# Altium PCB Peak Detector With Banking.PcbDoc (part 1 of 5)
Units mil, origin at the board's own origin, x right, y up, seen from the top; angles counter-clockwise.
Board outline 3330 x 2725 mil, 4 copper layers (TopLayer, GROUND, MidLayer1, BottomLayer); 549 components, 391 nets, 1594 pads, 460 vias.
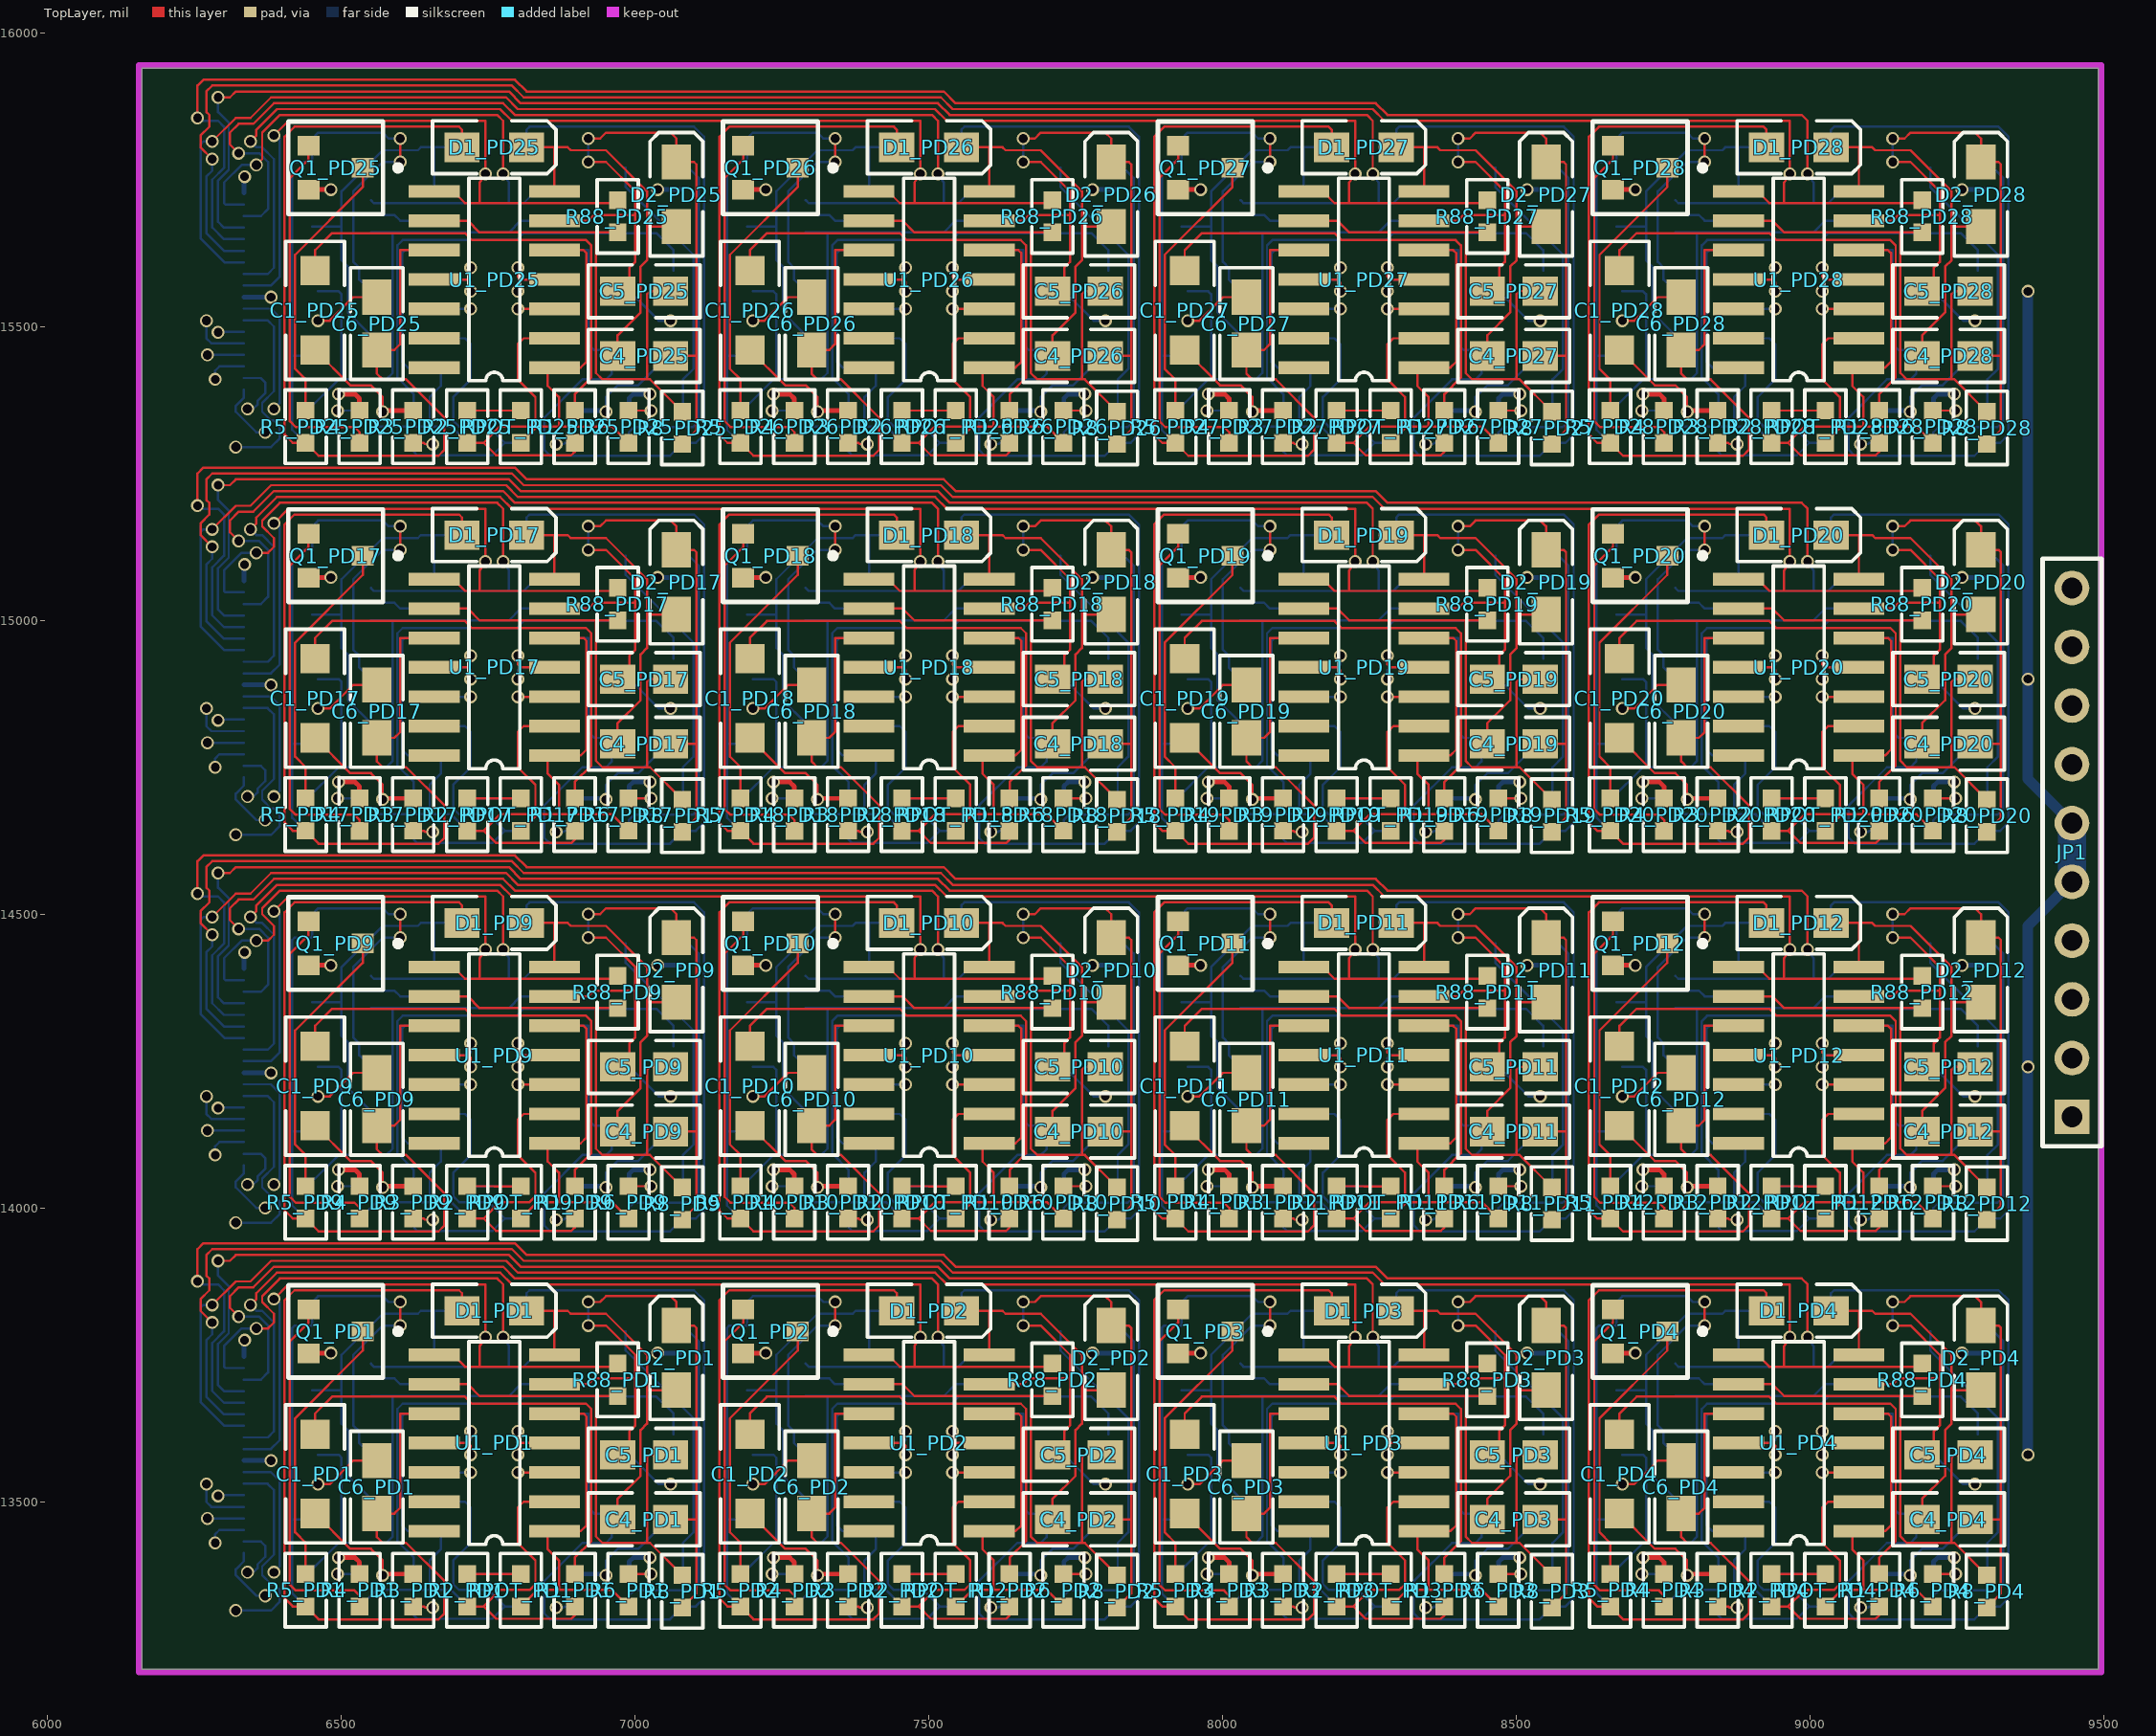
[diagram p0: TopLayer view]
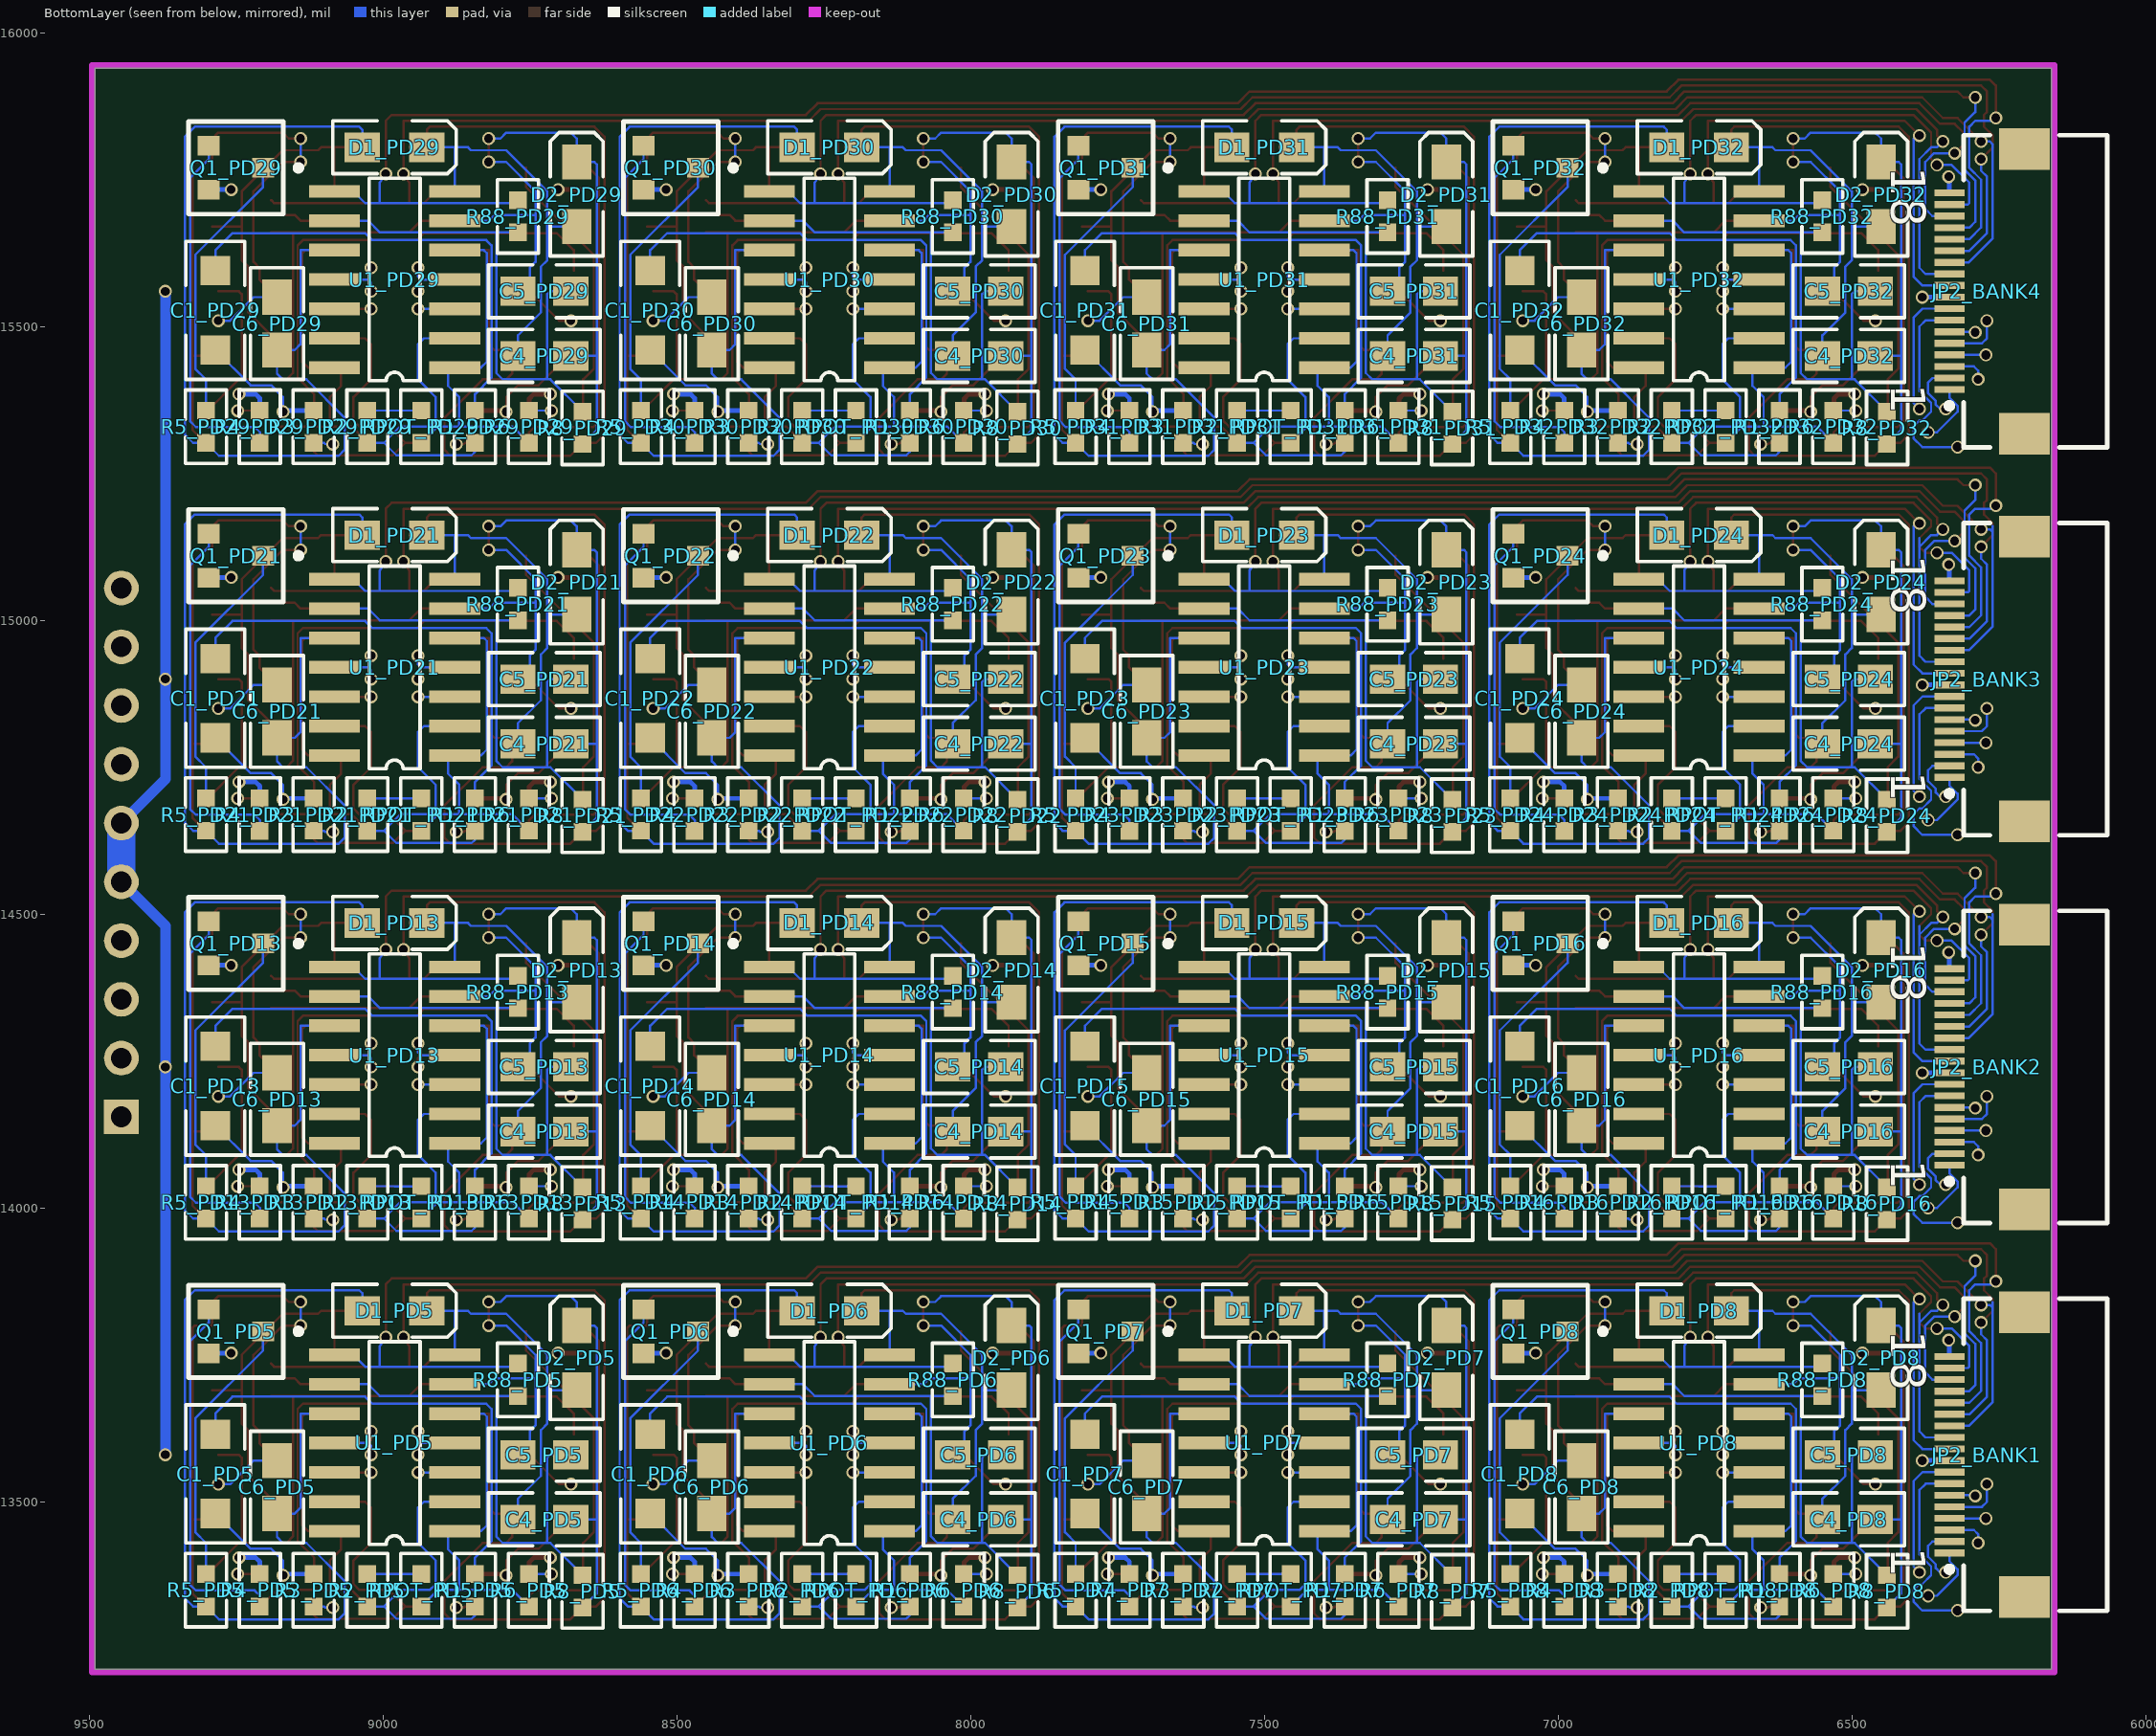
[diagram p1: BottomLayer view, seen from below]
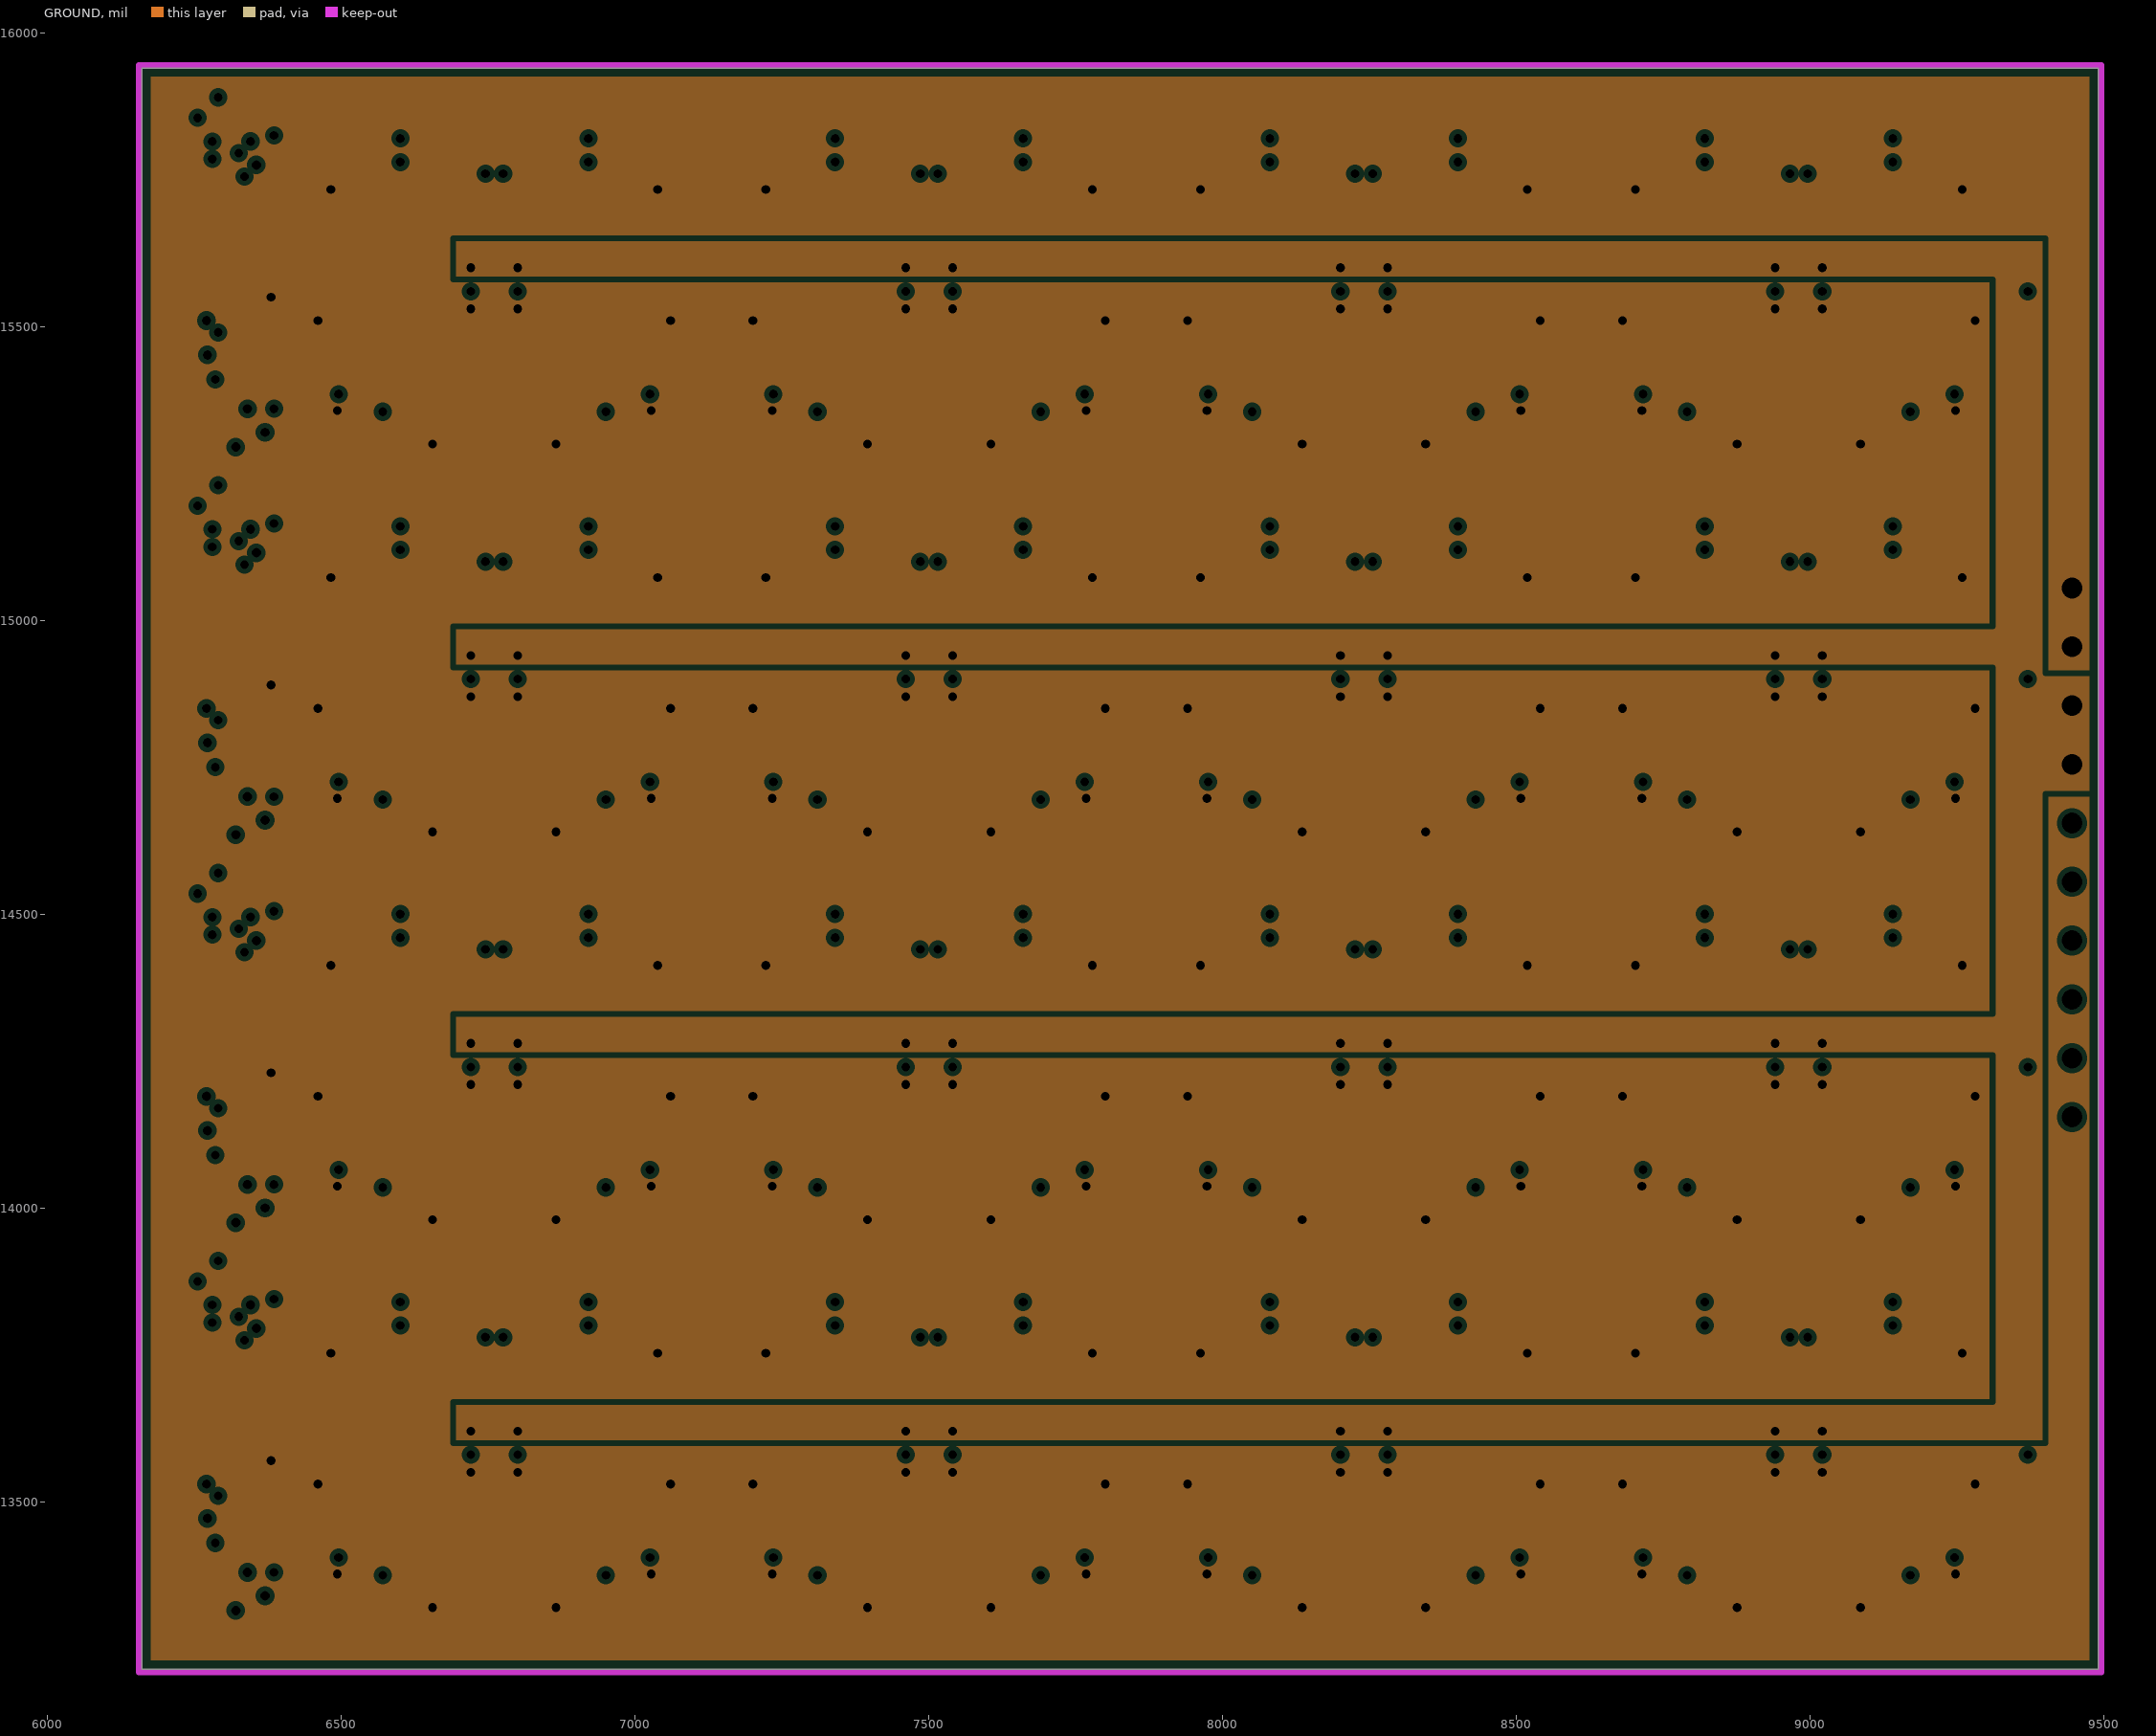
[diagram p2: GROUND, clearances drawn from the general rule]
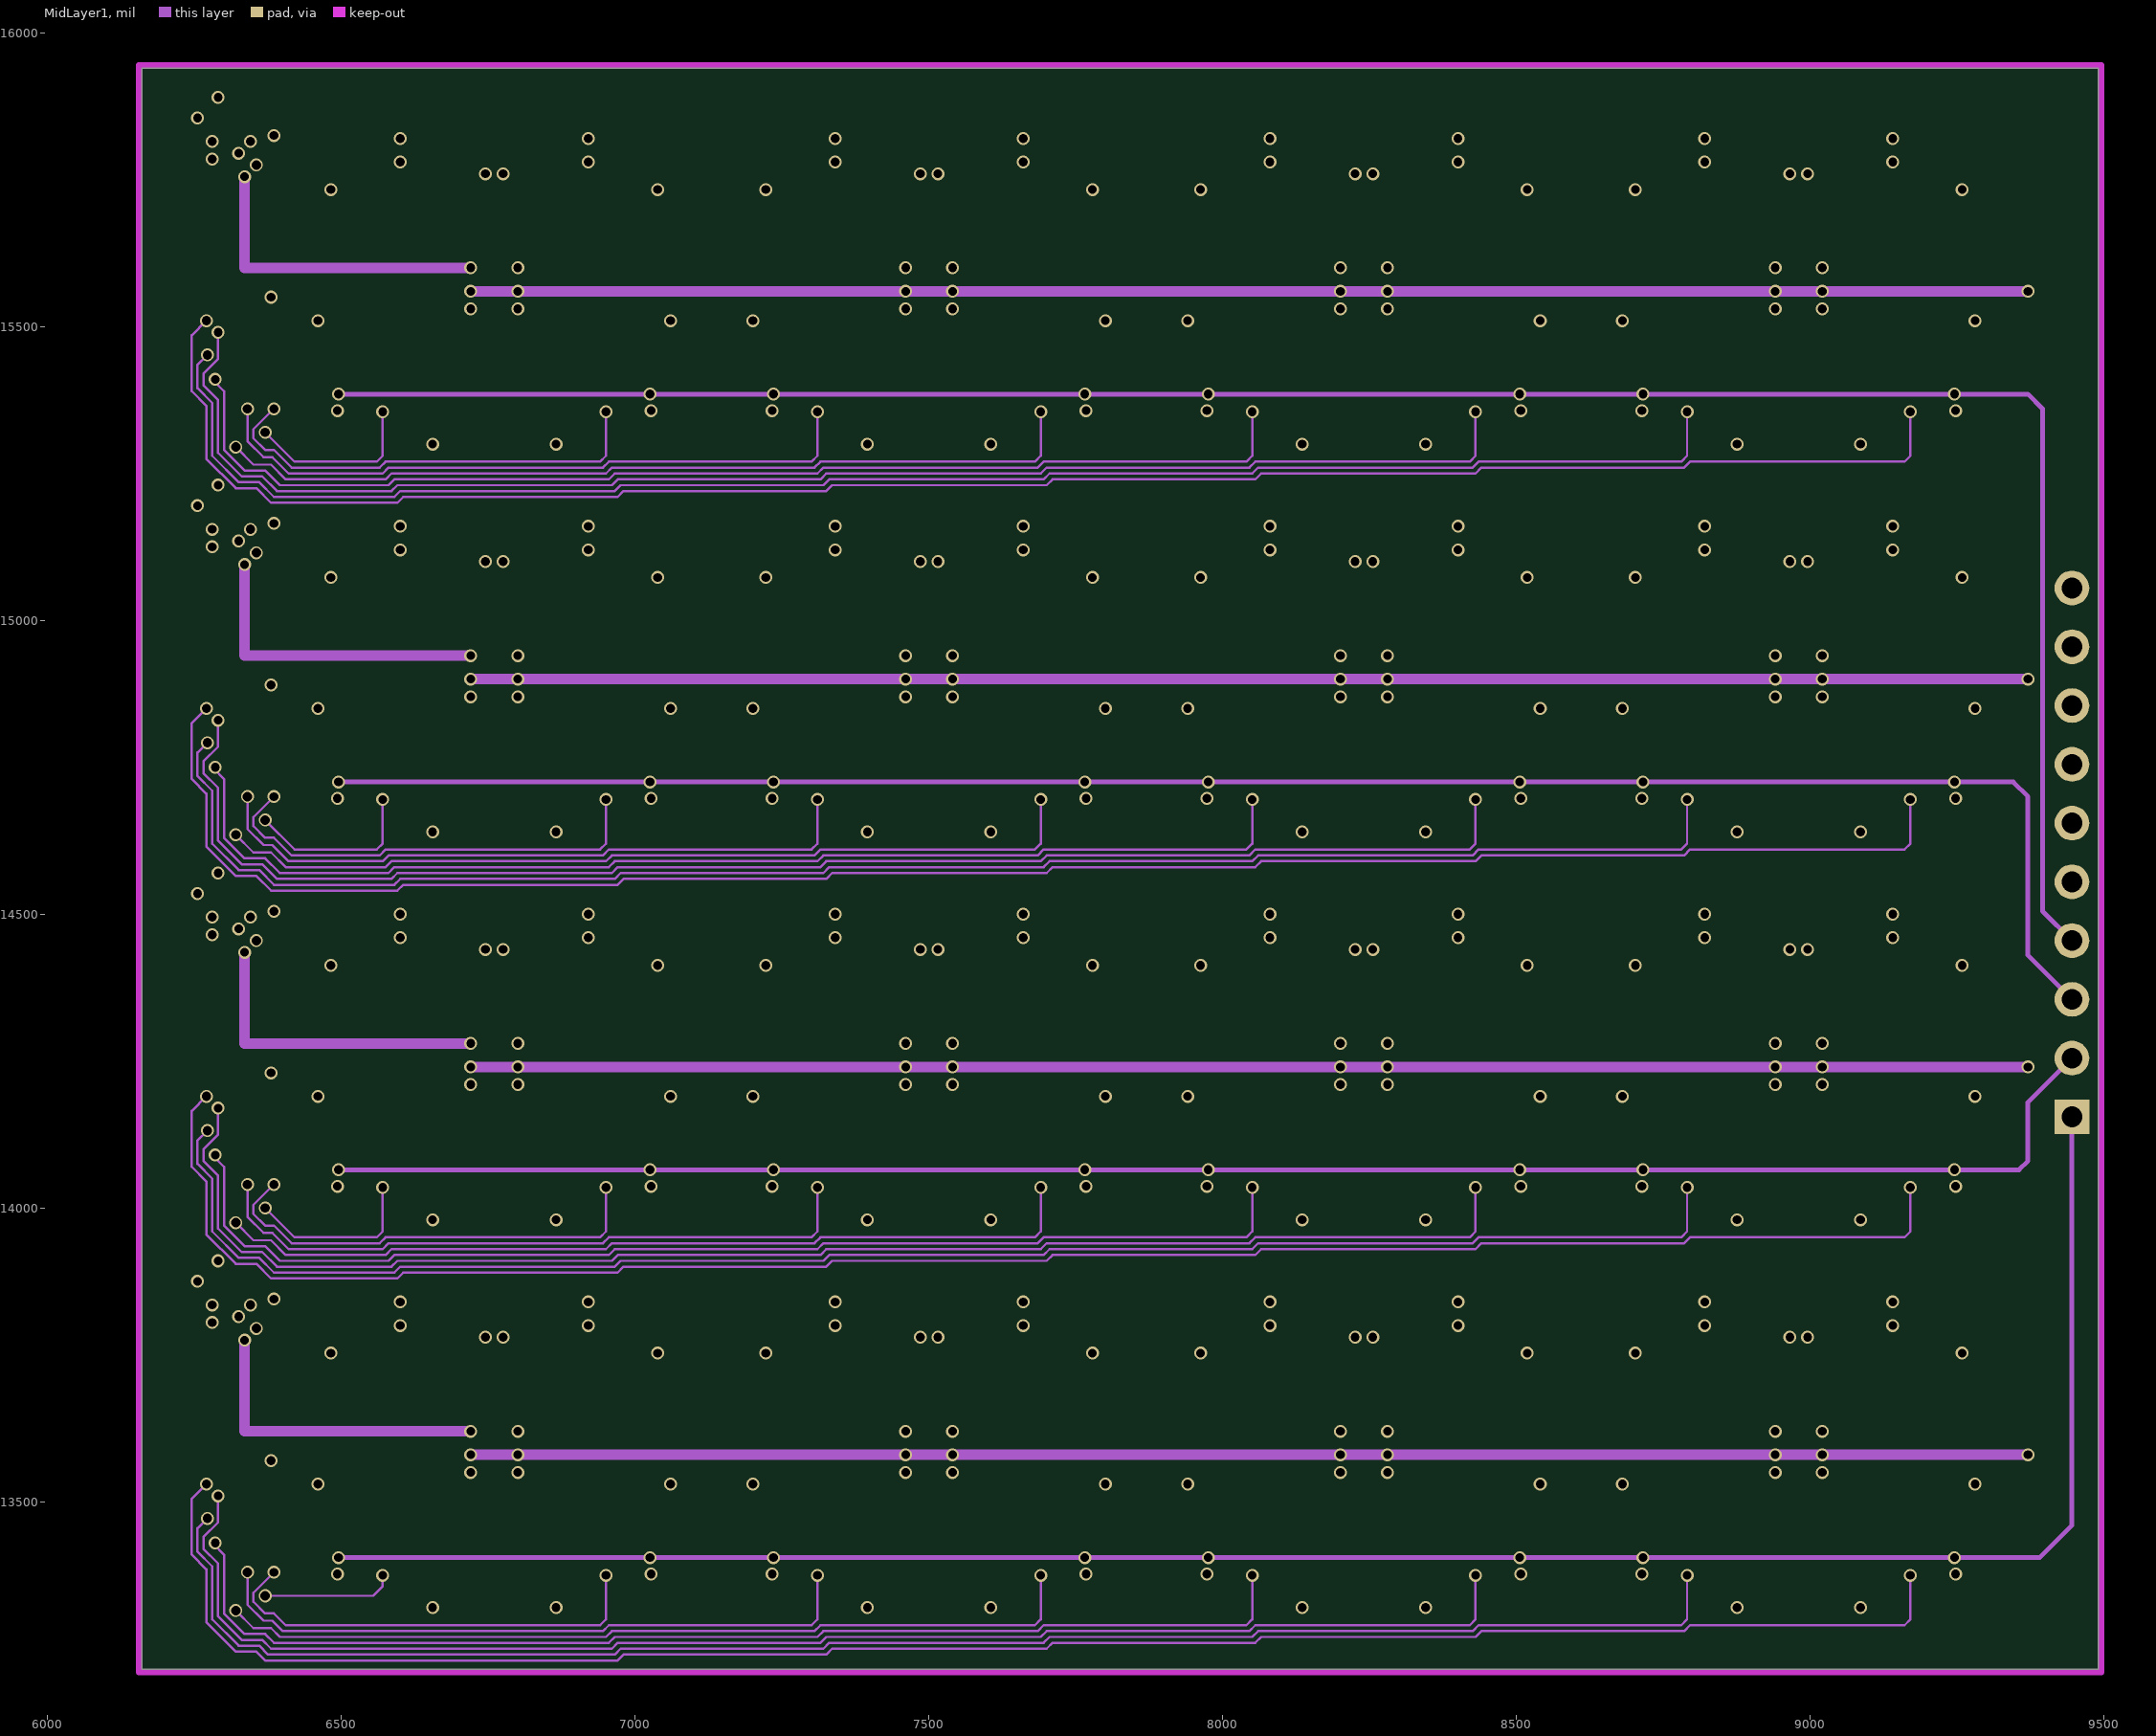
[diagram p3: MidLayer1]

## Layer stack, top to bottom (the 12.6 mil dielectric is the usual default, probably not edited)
TopLayer: signal copper 1.4
Dielectric: core 12.6, FR-4, Dk 4.8
GROUND: plane copper 1.4, net (Multiple Nets)
Dielectric: prepreg 12.6, FR-4, Dk 4.8
MidLayer1: signal copper 1.4
Dielectric: core 12.6, FR-4, Dk 4.8
BottomLayer: signal copper 1.4

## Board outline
6160,13215 9490,13215 9490,15940 6160,15940

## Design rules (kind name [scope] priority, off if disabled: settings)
Clearance "Overlapping Pads" [IsPad vs IsPad] p1: gap=0
Clearance "Overlapping Vias" [IsVia vs IsVia] p2: gap=0
Clearance [All] p3: gap=4
ComponentClearance [All] p1: gap=1 collisioncheckmode=3 verticalgap=10 showdistances=FALSE
FabricationTestPointUsage TestPointUsage [All] p1: valid=0 allowmultiple=FALSE
FabricationTestpoint Testpoint [All] p1: side=3 testpointundercomponent=TRUE minsize=40 maxsize=100 preferedsize=60 minholesize=20 maxholesize=40 preferedholesize=32 testpointgrid=1 allowsidetop=TRUE allowsidebottom=TRUE usegrid=TRUE gridtolerance=0.01
MaxMinImpedance [All] p1: minimum=1.000 maximum=10.00
PlaneClearance [All] p1: clearance=8
PlaneConnect PlaneConnect_Rails [InNet('VCC5') Or InNet('VSSM5')] p1: planeconnectstyle=Direct reliefexpansion=12 reliefentries=4 reliefconductorwidth=10 reliefairgap=10
PlaneConnect [All] p2: planeconnectstyle=Relief reliefexpansion=10 reliefentries=4 reliefconductorwidth=10 reliefairgap=10
PolygonConnect [All] p1: connectstyle=Relief reliefconductorwidth=10 reliefentries=4 polygonreliefangle="90 Angle"
RoomDefinition BANKA_PD8 [InComponentClass('BANKA_PD8')] p1: confinementstyle=ConfineIn formatcopy=TRUE lockcomponents=FALSE outline 7120,13295 6400,13295 6400,13865 7120,13865
RoomDefinition BANKB_PD8 [InComponentClass('BANKB_PD8')] p2: confinementstyle=ConfineIn formatcopy=TRUE lockcomponents=FALSE outline 7120,13955 6400,13955 6400,14525 7120,14525
RoomDefinition BANKC_PD8 [InComponentClass('BANKC_PD8')] p3: confinementstyle=ConfineIn formatcopy=TRUE lockcomponents=FALSE outline 7120,14615 6400,14615 6400,15185 7120,15185
RoomDefinition BANKD_PD8 [InComponentClass('BANKD_PD8')] p4: confinementstyle=ConfineIn formatcopy=TRUE lockcomponents=FALSE outline 7120,15275 6400,15275 6400,15845 7120,15845
RoomDefinition BANKA_PD7 [InComponentClass('BANKA_PD7')] p5: confinementstyle=ConfineIn formatcopy=TRUE lockcomponents=FALSE outline 7860,13295 7140,13295 7140,13865 7860,13865
RoomDefinition BANKB_PD7 [InComponentClass('BANKB_PD7')] p6: confinementstyle=ConfineIn formatcopy=TRUE lockcomponents=FALSE outline 7860,13955 7140,13955 7140,14525 7860,14525
RoomDefinition BANKC_PD7 [InComponentClass('BANKC_PD7')] p7: confinementstyle=ConfineIn formatcopy=TRUE lockcomponents=FALSE outline 7860,14615 7140,14615 7140,15185 7860,15185
RoomDefinition BANKD_PD7 [InComponentClass('BANKD_PD7')] p8: confinementstyle=ConfineIn formatcopy=TRUE lockcomponents=FALSE outline 7860,15275 7140,15275 7140,15845 7860,15845
RoomDefinition BANKA_PD6 [InComponentClass('BANKA_PD6')] p9: confinementstyle=ConfineIn formatcopy=TRUE lockcomponents=FALSE outline 8600,13295 7880,13295 7880,13865 8600,13865
RoomDefinition BANKB_PD6 [InComponentClass('BANKB_PD6')] p10: confinementstyle=ConfineIn formatcopy=TRUE lockcomponents=FALSE outline 8600,13955 7880,13955 7880,14525 8600,14525
RoomDefinition BANKC_PD6 [InComponentClass('BANKC_PD6')] p11: confinementstyle=ConfineIn formatcopy=TRUE lockcomponents=FALSE outline 8600,14615 7880,14615 7880,15185 8600,15185
RoomDefinition BANKD_PD6 [InComponentClass('BANKD_PD6')] p12: confinementstyle=ConfineIn formatcopy=TRUE lockcomponents=FALSE outline 8600,15275 7880,15275 7880,15845 8600,15845
RoomDefinition BANKA_PD5 [InComponentClass('BANKA_PD5')] p13: confinementstyle=ConfineIn formatcopy=TRUE lockcomponents=FALSE outline 9340,13295 8620,13295 8620,13865 9340,13865
RoomDefinition BANKB_PD5 [InComponentClass('BANKB_PD5')] p14: confinementstyle=ConfineIn formatcopy=TRUE lockcomponents=FALSE outline 9340,13955 8620,13955 8620,14525 9340,14525
RoomDefinition BANKC_PD5 [InComponentClass('BANKC_PD5')] p15: confinementstyle=ConfineIn formatcopy=TRUE lockcomponents=FALSE outline 9340,14615 8620,14615 8620,15185 9340,15185
RoomDefinition BANKD_PD5 [InComponentClass('BANKD_PD5')] p16: confinementstyle=ConfineIn formatcopy=TRUE lockcomponents=FALSE outline 9340,15275 8620,15275 8620,15845 9340,15845
RoomDefinition BANKA_PD4 [InComponentClass('BANKA_PD4')] p17: confinementstyle=ConfineIn formatcopy=TRUE lockcomponents=FALSE outline 8620,13295 9340,13295 9340,13865 8620,13865
RoomDefinition BANKB_PD4 [InComponentClass('BANKB_PD4')] p18: confinementstyle=ConfineIn formatcopy=TRUE lockcomponents=FALSE outline 8620,13955 9340,13955 9340,14525 8620,14525
RoomDefinition BANKC_PD4 [InComponentClass('BANKC_PD4')] p19: confinementstyle=ConfineIn formatcopy=TRUE lockcomponents=FALSE outline 8620,14615 9340,14615 9340,15185 8620,15185
RoomDefinition BANKD_PD4 [InComponentClass('BANKD_PD4')] p20: confinementstyle=ConfineIn formatcopy=TRUE lockcomponents=FALSE outline 8620,15275 9340,15275 9340,15845 8620,15845
RoomDefinition BANKA_PD3 [InComponentClass('BANKA_PD3')] p21: confinementstyle=ConfineIn formatcopy=TRUE lockcomponents=FALSE outline 7880,13295 8600,13295 8600,13865 7880,13865
RoomDefinition BANKB_PD3 [InComponentClass('BANKB_PD3')] p22: confinementstyle=ConfineIn formatcopy=TRUE lockcomponents=FALSE outline 7880,13955 8600,13955 8600,14525 7880,14525
RoomDefinition BANKC_PD3 [InComponentClass('BANKC_PD3')] p23: confinementstyle=ConfineIn formatcopy=TRUE lockcomponents=FALSE outline 7880,14615 8600,14615 8600,15185 7880,15185
RoomDefinition BANKD_PD3 [InComponentClass('BANKD_PD3')] p24: confinementstyle=ConfineIn formatcopy=TRUE lockcomponents=FALSE outline 7880,15275 8600,15275 8600,15845 7880,15845
RoomDefinition BANKA_PD2 [InComponentClass('BANKA_PD2')] p25: confinementstyle=ConfineIn formatcopy=TRUE lockcomponents=FALSE outline 7140,13295 7860,13295 7860,13865 7140,13865
RoomDefinition BANKB_PD2 [InComponentClass('BANKB_PD2')] p26: confinementstyle=ConfineIn formatcopy=TRUE lockcomponents=FALSE outline 7140,13955 7860,13955 7860,14525 7140,14525
RoomDefinition BANKC_PD2 [InComponentClass('BANKC_PD2')] p27: confinementstyle=ConfineIn formatcopy=TRUE lockcomponents=FALSE outline 7140,14615 7860,14615 7860,15185 7140,15185
RoomDefinition BANKD_PD2 [InComponentClass('BANKD_PD2')] p28: confinementstyle=ConfineIn formatcopy=TRUE lockcomponents=FALSE outline 7140,15275 7860,15275 7860,15845 7140,15845
RoomDefinition BANKA_PD1 [InComponentClass('BANKA_PD1')] p29: confinementstyle=ConfineIn formatcopy=TRUE lockcomponents=FALSE outline 6400,13295 7120,13295 7120,13865 6400,13865
RoomDefinition BANKB_PD1 [InComponentClass('BANKB_PD1')] p30: confinementstyle=ConfineIn formatcopy=TRUE lockcomponents=FALSE outline 6400,13955 7120,13955 7120,14525 6400,14525
RoomDefinition BANKC_PD1 [InComponentClass('BANKC_PD1')] p31: confinementstyle=ConfineIn formatcopy=TRUE lockcomponents=FALSE outline 6400,14615 7120,14615 7120,15185 6400,15185
RoomDefinition BANKD [InComponentClass('BANKD')] p32: confinementstyle=ConfineIn formatcopy=TRUE lockcomponents=FALSE outline 6060.34,15277.44 6060.34,15842.56 6440.29,15842.56 6440.29,15277.44
RoomDefinition BANKC [InComponentClass('BANKC')] p33: confinementstyle=ConfineIn formatcopy=TRUE lockcomponents=FALSE outline 6060.34,14617.44 6060.34,15182.56 6440.29,15182.56 6440.29,14617.44
RoomDefinition BANKA [InComponentClass('BANKA')] p34: confinementstyle=ConfineIn formatcopy=TRUE lockcomponents=FALSE outline 6060.34,13297.44 6060.34,13862.56 6440.29,13862.56 6440.29,13297.44
RoomDefinition BANKD_PD1 [InComponentClass('BANKD_PD1')] p35: confinementstyle=ConfineIn formatcopy=TRUE lockcomponents=FALSE outline 6400,15275 7120,15275 7120,15845 6400,15845
RoomDefinition "Peak Detector" [InComponentClass('Peak Detector')] p36: confinementstyle=ConfineIn formatcopy=TRUE lockcomponents=FALSE outline 9400,14100 9400,15109.87 9495,15109.87 9495,14100
RoomDefinition BANKB [InComponentClass('BANKB')] p37: confinementstyle=ConfineIn formatcopy=TRUE lockcomponents=FALSE outline 6060.34,13957.44 6060.34,14522.56 6440.29,14522.56 6440.29,13957.44
RoutingVias [All] p1: holewidth=15 width=22 viastyle="Through Hole" minholewidth=15 minwidth=22 maxholewidth=16 maxwidth=22
SilkscreenOverComponentPads [All] p1: minsilkscreentomaskgap=10
SolderMaskExpansion [All] p1: expansion=4
Width "Power Nets" [InNet('VCC5') Or InNet('VSSM5')] p1: maxlimit=18 minlimit=4 preferedwidth=18
Width [All] p2: maxlimit=12 minlimit=4 preferedwidth=4
22 further rules are at their usual default settings.

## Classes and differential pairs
component class BANKA_PD8: C1_PD8 C4_PD8 C5_PD8 C6_PD8 D1_PD8 D2_PD8 Q1_PD8 R1_PD8 R2_PD8 R3_PD8 R4_PD8 R5_PD8 R6_PD8 R8_PD8 R88_PD8 RPOT_PD8 U1_PD8
component class BANKA_PD7: C1_PD7 C4_PD7 C5_PD7 C6_PD7 D1_PD7 D2_PD7 Q1_PD7 R1_PD7 R2_PD7 R3_PD7 R4_PD7 R5_PD7 R6_PD7 R8_PD7 R88_PD7 RPOT_PD7 U1_PD7
component class BANKA_PD6: C1_PD6 C4_PD6 C5_PD6 C6_PD6 D1_PD6 D2_PD6 Q1_PD6 R1_PD6 R2_PD6 R3_PD6 R4_PD6 R5_PD6 R6_PD6 R8_PD6 R88_PD6 RPOT_PD6 U1_PD6
component class BANKA_PD5: C1_PD5 C4_PD5 C5_PD5 C6_PD5 D1_PD5 D2_PD5 Q1_PD5 R1_PD5 R2_PD5 R3_PD5 R4_PD5 R5_PD5 R6_PD5 R8_PD5 R88_PD5 RPOT_PD5 U1_PD5
component class BANKA_PD1: C1_PD1 C4_PD1 C5_PD1 C6_PD1 D1_PD1 D2_PD1 Q1_PD1 R1_PD1 R2_PD1 R3_PD1 R4_PD1 R5_PD1 R6_PD1 R8_PD1 R88_PD1 RPOT_PD1 U1_PD1
component class BANKA_PD2: C1_PD2 C4_PD2 C5_PD2 C6_PD2 D1_PD2 D2_PD2 Q1_PD2 R1_PD2 R2_PD2 R3_PD2 R4_PD2 R5_PD2 R6_PD2 R8_PD2 R88_PD2 RPOT_PD2 U1_PD2
component class BANKA_PD3: C1_PD3 C4_PD3 C5_PD3 C6_PD3 D1_PD3 D2_PD3 Q1_PD3 R1_PD3 R2_PD3 R3_PD3 R4_PD3 R5_PD3 R6_PD3 R8_PD3 R88_PD3 RPOT_PD3 U1_PD3
component class BANKA_PD4: C1_PD4 C4_PD4 C5_PD4 C6_PD4 D1_PD4 D2_PD4 Q1_PD4 R1_PD4 R2_PD4 R3_PD4 R4_PD4 R5_PD4 R6_PD4 R8_PD4 R88_PD4 RPOT_PD4 U1_PD4
component class BANKA: JP2_BANK1
component class BANKB_PD1: C1_PD9 C4_PD9 C5_PD9 C6_PD9 D1_PD9 D2_PD9 Q1_PD9 R1_PD9 R2_PD9 R3_PD9 R4_PD9 R5_PD9 R6_PD9 R8_PD9 R88_PD9 RPOT_PD9 U1_PD9
component class BANKB_PD2: C1_PD10 C4_PD10 C5_PD10 C6_PD10 D1_PD10 D2_PD10 Q1_PD10 R1_PD10 R2_PD10 R3_PD10 R4_PD10 R5_PD10 R6_PD10 R8_PD10 R88_PD10 RPOT_PD10 U1_PD10
component class BANKB_PD3: C1_PD11 C4_PD11 C5_PD11 C6_PD11 D1_PD11 D2_PD11 Q1_PD11 R1_PD11 R2_PD11 R3_PD11 R4_PD11 R5_PD11 R6_PD11 R8_PD11 R88_PD11 RPOT_PD11 U1_PD11
component class BANKB_PD4: C1_PD12 C4_PD12 C5_PD12 C6_PD12 D1_PD12 D2_PD12 Q1_PD12 R1_PD12 R2_PD12 R3_PD12 R4_PD12 R5_PD12 R6_PD12 R8_PD12 R88_PD12 RPOT_PD12 U1_PD12
component class BANKB_PD5: C1_PD13 C4_PD13 C5_PD13 C6_PD13 D1_PD13 D2_PD13 Q1_PD13 R1_PD13 R2_PD13 R3_PD13 R4_PD13 R5_PD13 R6_PD13 R8_PD13 R88_PD13 RPOT_PD13 U1_PD13
component class BANKB_PD6: C1_PD14 C4_PD14 C5_PD14 C6_PD14 D1_PD14 D2_PD14 Q1_PD14 R1_PD14 R2_PD14 R3_PD14 R4_PD14 R5_PD14 R6_PD14 R8_PD14 R88_PD14 RPOT_PD14 U1_PD14
component class BANKB_PD7: C1_PD15 C4_PD15 C5_PD15 C6_PD15 D1_PD15 D2_PD15 Q1_PD15 R1_PD15 R2_PD15 R3_PD15 R4_PD15 R5_PD15 R6_PD15 R8_PD15 R88_PD15 RPOT_PD15 U1_PD15
component class BANKB_PD8: C1_PD16 C4_PD16 C5_PD16 C6_PD16 D1_PD16 D2_PD16 Q1_PD16 R1_PD16 R2_PD16 R3_PD16 R4_PD16 R5_PD16 R6_PD16 R8_PD16 R88_PD16 RPOT_PD16 U1_PD16
component class BANKB: JP2_BANK2
component class BANKC_PD1: C1_PD17 C4_PD17 C5_PD17 C6_PD17 D1_PD17 D2_PD17 Q1_PD17 R1_PD17 R2_PD17 R3_PD17 R4_PD17 R5_PD17 R6_PD17 R8_PD17 R88_PD17 RPOT_PD17 U1_PD17
component class BANKC_PD2: C1_PD18 C4_PD18 C5_PD18 C6_PD18 D1_PD18 D2_PD18 Q1_PD18 R1_PD18 R2_PD18 R3_PD18 R4_PD18 R5_PD18 R6_PD18 R8_PD18 R88_PD18 RPOT_PD18 U1_PD18
component class BANKC_PD3: C1_PD19 C4_PD19 C5_PD19 C6_PD19 D1_PD19 D2_PD19 Q1_PD19 R1_PD19 R2_PD19 R3_PD19 R4_PD19 R5_PD19 R6_PD19 R8_PD19 R88_PD19 RPOT_PD19 U1_PD19
component class BANKC_PD4: C1_PD20 C4_PD20 C5_PD20 C6_PD20 D1_PD20 D2_PD20 Q1_PD20 R1_PD20 R2_PD20 R3_PD20 R4_PD20 R5_PD20 R6_PD20 R8_PD20 R88_PD20 RPOT_PD20 U1_PD20
component class BANKC_PD5: C1_PD21 C4_PD21 C5_PD21 C6_PD21 D1_PD21 D2_PD21 Q1_PD21 R1_PD21 R2_PD21 R3_PD21 R4_PD21 R5_PD21 R6_PD21 R8_PD21 R88_PD21 RPOT_PD21 U1_PD21
component class BANKC_PD6: C1_PD22 C4_PD22 C5_PD22 C6_PD22 D1_PD22 D2_PD22 Q1_PD22 R1_PD22 R2_PD22 R3_PD22 R4_PD22 R5_PD22 R6_PD22 R8_PD22 R88_PD22 RPOT_PD22 U1_PD22
component class BANKC_PD7: C1_PD23 C4_PD23 C5_PD23 C6_PD23 D1_PD23 D2_PD23 Q1_PD23 R1_PD23 R2_PD23 R3_PD23 R4_PD23 R5_PD23 R6_PD23 R8_PD23 R88_PD23 RPOT_PD23 U1_PD23
component class BANKC_PD8: C1_PD24 C4_PD24 C5_PD24 C6_PD24 D1_PD24 D2_PD24 Q1_PD24 R1_PD24 R2_PD24 R3_PD24 R4_PD24 R5_PD24 R6_PD24 R8_PD24 R88_PD24 RPOT_PD24 U1_PD24
component class BANKC: JP2_BANK3
component class BANKD_PD1: C1_PD25 C4_PD25 C5_PD25 C6_PD25 D1_PD25 D2_PD25 Q1_PD25 R1_PD25 R2_PD25 R3_PD25 R4_PD25 R5_PD25 R6_PD25 R8_PD25 R88_PD25 RPOT_PD25 U1_PD25
component class BANKD_PD2: C1_PD26 C4_PD26 C5_PD26 C6_PD26 D1_PD26 D2_PD26 Q1_PD26 R1_PD26 R2_PD26 R3_PD26 R4_PD26 R5_PD26 R6_PD26 R8_PD26 R88_PD26 RPOT_PD26 U1_PD26
component class BANKD_PD3: C1_PD27 C4_PD27 C5_PD27 C6_PD27 D1_PD27 D2_PD27 Q1_PD27 R1_PD27 R2_PD27 R3_PD27 R4_PD27 R5_PD27 R6_PD27 R8_PD27 R88_PD27 RPOT_PD27 U1_PD27
component class BANKD_PD4: C1_PD28 C4_PD28 C5_PD28 C6_PD28 D1_PD28 D2_PD28 Q1_PD28 R1_PD28 R2_PD28 R3_PD28 R4_PD28 R5_PD28 R6_PD28 R8_PD28 R88_PD28 RPOT_PD28 U1_PD28
component class BANKD_PD5: C1_PD29 C4_PD29 C5_PD29 C6_PD29 D1_PD29 D2_PD29 Q1_PD29 R1_PD29 R2_PD29 R3_PD29 R4_PD29 R5_PD29 R6_PD29 R8_PD29 R88_PD29 RPOT_PD29 U1_PD29
component class BANKD_PD6: C1_PD30 C4_PD30 C5_PD30 C6_PD30 D1_PD30 D2_PD30 Q1_PD30 R1_PD30 R2_PD30 R3_PD30 R4_PD30 R5_PD30 R6_PD30 R8_PD30 R88_PD30 RPOT_PD30 U1_PD30
component class BANKD_PD7: C1_PD31 C4_PD31 C5_PD31 C6_PD31 D1_PD31 D2_PD31 Q1_PD31 R1_PD31 R2_PD31 R3_PD31 R4_PD31 R5_PD31 R6_PD31 R8_PD31 R88_PD31 RPOT_PD31 U1_PD31
component class BANKD_PD8: C1_PD32 C4_PD32 C5_PD32 C6_PD32 D1_PD32 D2_PD32 Q1_PD32 R1_PD32 R2_PD32 R3_PD32 R4_PD32 R5_PD32 R6_PD32 R8_PD32 R88_PD32 RPOT_PD32 U1_PD32
component class BANKD: JP2_BANK4
component class "Peak Detector": JP1
channel class Bank: BANKA BANKB BANKC BANKD
channel class "Peak Detector - channel": BANKA_PD1 BANKA_PD2 BANKA_PD3 BANKA_PD4 BANKA_PD5 BANKA_PD6 BANKA_PD7 BANKA_PD8 BANKB_PD1 BANKB_PD2 BANKB_PD3 BANKB_PD4 BANKB_PD5 BANKB_PD6 BANKB_PD7 BANKB_PD8 BANKC_PD1 BANKC_PD2 BANKC_PD3 BANKC_PD4 BANKC_PD5 BANKC_PD6 BANKC_PD7 BANKC_PD8 BANKD_PD1 BANKD_PD2 BANKD_PD3 BANKD_PD4 BANKD_PD5 BANKD_PD6 BANKD_PD7 BANKD_PD8
net class OFF[1..4]: OFF1 OFF2 OFF3 OFF4

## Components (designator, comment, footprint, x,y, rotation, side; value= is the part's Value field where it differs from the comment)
C1_PD1 "10uF" 1206 6455,13615 r270 top (schematic designator C1)
C1_PD2 "10uF" 1206 7195,13615 r270 top (schematic designator C1)
C1_PD3 "10uF" 1206 7935,13615 r270 top (schematic designator C1)
C1_PD4 "10uF" 1206 8675,13615 r270 top (schematic designator C1)
C1_PD5 "10uF" 1206 9285,13615 r270 bottom (schematic designator C1)
C1_PD6 "10uF" 1206 8545,13615 r270 bottom (schematic designator C1)
C1_PD7 "10uF" 1206 7805,13615 r270 bottom (schematic designator C1)
C1_PD8 "10uF" 1206 7065,13615 r270 bottom (schematic designator C1)
C1_PD9 "10uF" 1206 6455,14275 r270 top (schematic designator C1)
C1_PD10 "10uF" 1206 7195,14275 r270 top (schematic designator C1)
C1_PD11 "10uF" 1206 7935,14275 r270 top (schematic designator C1)
C1_PD12 "10uF" 1206 8675,14275 r270 top (schematic designator C1)
C1_PD13 "10uF" 1206 9285,14275 r270 bottom (schematic designator C1)
C1_PD14 "10uF" 1206 8545,14275 r270 bottom (schematic designator C1)
C1_PD15 "10uF" 1206 7805,14275 r270 bottom (schematic designator C1)
C1_PD16 "10uF" 1206 7065,14275 r270 bottom (schematic designator C1)
C1_PD17 "10uF" 1206 6455,14935 r270 top (schematic designator C1)
C1_PD18 "10uF" 1206 7195,14935 r270 top (schematic designator C1)
C1_PD19 "10uF" 1206 7935,14935 r270 top (schematic designator C1)
C1_PD20 "10uF" 1206 8675,14935 r270 top (schematic designator C1)
C1_PD21 "10uF" 1206 9285,14935 r270 bottom (schematic designator C1)
C1_PD22 "10uF" 1206 8545,14935 r270 bottom (schematic designator C1)
C1_PD23 "10uF" 1206 7805,14935 r270 bottom (schematic designator C1)
C1_PD24 "10uF" 1206 7065,14935 r270 bottom (schematic designator C1)
C1_PD25 "10uF" 1206 6455,15595 r270 top (schematic designator C1)
C1_PD26 "10uF" 1206 7195,15595 r270 top (schematic designator C1)
C1_PD27 "10uF" 1206 7935,15595 r270 top (schematic designator C1)
C1_PD28 "10uF" 1206 8675,15595 r270 top (schematic designator C1)
C1_PD29 "10uF" 1206 9285,15595 r270 bottom (schematic designator C1)
C1_PD30 "10uF" 1206 8545,15595 r270 bottom (schematic designator C1)
C1_PD31 "10uF" 1206 7805,15595 r270 bottom (schematic designator C1)
C1_PD32 "10uF" 1206 7065,15595 r270 bottom (schematic designator C1)
C4_PD1 "15pF" 0805 7060,13470 r180 top (schematic designator C4)
C4_PD2 "15pF" 0805 7800,13470 r180 top (schematic designator C4)
C4_PD3 "15pF" 0805 8540,13470 r180 top (schematic designator C4)
C4_PD4 "15pF" 0805 9280,13470 r180 top (schematic designator C4)
C4_PD5 "15pF" 0805 8680,13470 r0 bottom (schematic designator C4)
C4_PD6 "15pF" 0805 7940,13470 r0 bottom (schematic designator C4)
C4_PD7 "15pF" 0805 7200,13470 r0 bottom (schematic designator C4)
C4_PD8 "15pF" 0805 6460,13470 r0 bottom (schematic designator C4)
C4_PD9 "15pF" 0805 7060,14130 r180 top (schematic designator C4)
C4_PD10 "15pF" 0805 7800,14130 r180 top (schematic designator C4)
C4_PD11 "15pF" 0805 8540,14130 r180 top (schematic designator C4)
C4_PD12 "15pF" 0805 9280,14130 r180 top (schematic designator C4)
C4_PD13 "15pF" 0805 8680,14130 r0 bottom (schematic designator C4)
C4_PD14 "15pF" 0805 7940,14130 r0 bottom (schematic designator C4)
C4_PD15 "15pF" 0805 7200,14130 r0 bottom (schematic designator C4)
C4_PD16 "15pF" 0805 6460,14130 r0 bottom (schematic designator C4)
C4_PD17 "15pF" 0805 7060,14790 r180 top (schematic designator C4)
C4_PD18 "15pF" 0805 7800,14790 r180 top (schematic designator C4)
C4_PD19 "15pF" 0805 8540,14790 r180 top (schematic designator C4)
C4_PD20 "15pF" 0805 9280,14790 r180 top (schematic designator C4)
C4_PD21 "15pF" 0805 8680,14790 r0 bottom (schematic designator C4)
C4_PD22 "15pF" 0805 7940,14790 r0 bottom (schematic designator C4)
C4_PD23 "15pF" 0805 7200,14790 r0 bottom (schematic designator C4)
C4_PD24 "15pF" 0805 6460,14790 r0 bottom (schematic designator C4)
C4_PD25 "15pF" 0805 7060,15450 r180 top (schematic designator C4)
C4_PD26 "15pF" 0805 7800,15450 r180 top (schematic designator C4)
C4_PD27 "15pF" 0805 8540,15450 r180 top (schematic designator C4)
C4_PD28 "15pF" 0805 9280,15450 r180 top (schematic designator C4)
C4_PD29 "15pF" 0805 8680,15450 r0 bottom (schematic designator C4)
C4_PD30 "15pF" 0805 7940,15450 r0 bottom (schematic designator C4)
C4_PD31 "15pF" 0805 7200,15450 r0 bottom (schematic designator C4)
C4_PD32 "15pF" 0805 6460,15450 r0 bottom (schematic designator C4)
C5_PD1 "4.7pF" 0805 6970,13580 r0 top (schematic designator C5)
C5_PD2 "4.7pF" 0805 7710,13580 r0 top (schematic designator C5)
C5_PD3 "4.7pF" 0805 8450,13580 r0 top (schematic designator C5)
C5_PD4 "4.7pF" 0805 9190,13580 r0 top (schematic designator C5)
C5_PD5 "4.7pF" 0805 8770,13580 r180 bottom (schematic designator C5)
C5_PD6 "4.7pF" 0805 8030,13580 r180 bottom (schematic designator C5)
C5_PD7 "4.7pF" 0805 7290,13580 r180 bottom (schematic designator C5)
C5_PD8 "4.7pF" 0805 6550,13580 r180 bottom (schematic designator C5)
C5_PD9 "4.7pF" 0805 6970,14240 r0 top (schematic designator C5)
C5_PD10 "4.7pF" 0805 7710,14240 r0 top (schematic designator C5)
C5_PD11 "4.7pF" 0805 8450,14240 r0 top (schematic designator C5)
C5_PD12 "4.7pF" 0805 9190,14240 r0 top (schematic designator C5)
C5_PD13 "4.7pF" 0805 8770,14240 r180 bottom (schematic designator C5)
C5_PD14 "4.7pF" 0805 8030,14240 r180 bottom (schematic designator C5)
C5_PD15 "4.7pF" 0805 7290,14240 r180 bottom (schematic designator C5)
C5_PD16 "4.7pF" 0805 6550,14240 r180 bottom (schematic designator C5)
C5_PD17 "4.7pF" 0805 6970,14900 r0 top (schematic designator C5)
C5_PD18 "4.7pF" 0805 7710,14900 r0 top (schematic designator C5)
C5_PD19 "4.7pF" 0805 8450,14900 r0 top (schematic designator C5)
C5_PD20 "4.7pF" 0805 9190,14900 r0 top (schematic designator C5)
C5_PD21 "4.7pF" 0805 8770,14900 r180 bottom (schematic designator C5)
C5_PD22 "4.7pF" 0805 8030,14900 r180 bottom (schematic designator C5)
C5_PD23 "4.7pF" 0805 7290,14900 r180 bottom (schematic designator C5)
C5_PD24 "4.7pF" 0805 6550,14900 r180 bottom (schematic designator C5)
C5_PD25 "4.7pF" 0805 6970,15560 r0 top (schematic designator C5)
C5_PD26 "4.7pF" 0805 7710,15560 r0 top (schematic designator C5)
C5_PD27 "4.7pF" 0805 8450,15560 r0 top (schematic designator C5)
C5_PD28 "4.7pF" 0805 9190,15560 r0 top (schematic designator C5)
C5_PD29 "4.7pF" 0805 8770,15560 r180 bottom (schematic designator C5)
C5_PD30 "4.7pF" 0805 8030,15560 r180 bottom (schematic designator C5)
C5_PD31 "4.7pF" 0805 7290,15560 r180 bottom (schematic designator C5)
C5_PD32 "4.7pF" 0805 6550,15560 r180 bottom (schematic designator C5)
C6_PD1 "1.0n" 0805 6560,13570 r270 top (schematic designator C6)
C6_PD2 "1.0n" 0805 7300,13570 r270 top (schematic designator C6)
C6_PD3 "1.0n" 0805 8040,13570 r270 top (schematic designator C6)
C6_PD4 "1.0n" 0805 8780,13570 r270 top (schematic designator C6)
C6_PD5 "1.0n" 0805 9180,13570 r270 bottom (schematic designator C6)
C6_PD6 "1.0n" 0805 8440,13570 r270 bottom (schematic designator C6)
C6_PD7 "1.0n" 0805 7700,13570 r270 bottom (schematic designator C6)
C6_PD8 "1.0n" 0805 6960,13570 r270 bottom (schematic designator C6)
C6_PD9 "1.0n" 0805 6560,14230 r270 top (schematic designator C6)
C6_PD10 "1.0n" 0805 7300,14230 r270 top (schematic designator C6)
C6_PD11 "1.0n" 0805 8040,14230 r270 top (schematic designator C6)
C6_PD12 "1.0n" 0805 8780,14230 r270 top (schematic designator C6)
C6_PD13 "1.0n" 0805 9180,14230 r270 bottom (schematic designator C6)
C6_PD14 "1.0n" 0805 8440,14230 r270 bottom (schematic designator C6)
C6_PD15 "1.0n" 0805 7700,14230 r270 bottom (schematic designator C6)
C6_PD16 "1.0n" 0805 6960,14230 r270 bottom (schematic designator C6)
C6_PD17 "1.0n" 0805 6560,14890 r270 top (schematic designator C6)
C6_PD18 "1.0n" 0805 7300,14890 r270 top (schematic designator C6)
C6_PD19 "1.0n" 0805 8040,14890 r270 top (schematic designator C6)
C6_PD20 "1.0n" 0805 8780,14890 r270 top (schematic designator C6)
C6_PD21 "1.0n" 0805 9180,14890 r270 bottom (schematic designator C6)
C6_PD22 "1.0n" 0805 8440,14890 r270 bottom (schematic designator C6)
C6_PD23 "1.0n" 0805 7700,14890 r270 bottom (schematic designator C6)
C6_PD24 "1.0n" 0805 6960,14890 r270 bottom (schematic designator C6)
C6_PD25 "1.0n" 0805 6560,15550 r270 top (schematic designator C6)
C6_PD26 "1.0n" 0805 7300,15550 r270 top (schematic designator C6)
C6_PD27 "1.0n" 0805 8040,15550 r270 top (schematic designator C6)
C6_PD28 "1.0n" 0805 8780,15550 r270 top (schematic designator C6)
C6_PD29 "1.0n" 0805 9180,15550 r270 bottom (schematic designator C6)
C6_PD30 "1.0n" 0805 8440,15550 r270 bottom (schematic designator C6)
C6_PD31 "1.0n" 0805 7700,15550 r270 bottom (schematic designator C6)
C6_PD32 "1.0n" 0805 6960,15550 r270 bottom (schematic designator C6)
D1_PD1 "1N914" 3216 6815,13825 r0 top (schematic designator D1)
D1_PD2 "1N914" 3216 7555,13825 r0 top (schematic designator D1)
D1_PD3 "1N914" 3216 8295,13825 r0 top (schematic designator D1)
D1_PD4 "1N914" 3216 9035,13825 r0 top (schematic designator D1)
D1_PD5 "1N914" 3216 8925,13825 r180 bottom (schematic designator D1)
D1_PD6 "1N914" 3216 8185,13825 r180 bottom (schematic designator D1)
D1_PD7 "1N914" 3216 7445,13825 r180 bottom (schematic designator D1)
D1_PD8 "1N914" 3216 6705,13825 r180 bottom (schematic designator D1)
D1_PD9 "1N914" 3216 6815,14485 r0 top (schematic designator D1)
D1_PD10 "1N914" 3216 7555,14485 r0 top (schematic designator D1)
D1_PD11 "1N914" 3216 8295,14485 r0 top (schematic designator D1)
D1_PD12 "1N914" 3216 9035,14485 r0 top (schematic designator D1)
D1_PD13 "1N914" 3216 8925,14485 r180 bottom (schematic designator D1)
D1_PD14 "1N914" 3216 8185,14485 r180 bottom (schematic designator D1)
D1_PD15 "1N914" 3216 7445,14485 r180 bottom (schematic designator D1)
D1_PD16 "1N914" 3216 6705,14485 r180 bottom (schematic designator D1)
D1_PD17 "1N914" 3216 6815,15145 r0 top (schematic designator D1)
D1_PD18 "1N914" 3216 7555,15145 r0 top (schematic designator D1)
D1_PD19 "1N914" 3216 8295,15145 r0 top (schematic designator D1)
D1_PD20 "1N914" 3216 9035,15145 r0 top (schematic designator D1)
D1_PD21 "1N914" 3216 8925,15145 r180 bottom (schematic designator D1)
D1_PD22 "1N914" 3216 8185,15145 r180 bottom (schematic designator D1)
D1_PD23 "1N914" 3216 7445,15145 r180 bottom (schematic designator D1)
D1_PD24 "1N914" 3216 6705,15145 r180 bottom (schematic designator D1)
D1_PD25 "1N914" 3216 6815,15805 r0 top (schematic designator D1)
D1_PD26 "1N914" 3216 7555,15805 r0 top (schematic designator D1)
D1_PD27 "1N914" 3216 8295,15805 r0 top (schematic designator D1)
D1_PD28 "1N914" 3216 9035,15805 r0 top (schematic designator D1)
D1_PD29 "1N914" 3216 8925,15805 r180 bottom (schematic designator D1)
D1_PD30 "1N914" 3216 8185,15805 r180 bottom (schematic designator D1)
D1_PD31 "1N914" 3216 7445,15805 r180 bottom (schematic designator D1)
D1_PD32 "1N914" 3216 6705,15805 r180 bottom (schematic designator D1)
D2_PD1 "1N914" 3216 7070,13800 r90 top (schematic designator D2)
D2_PD2 "1N914" 3216 7810,13800 r90 top (schematic designator D2)
D2_PD3 "1N914" 3216 8550,13800 r90 top (schematic designator D2)
D2_PD4 "1N914" 3216 9290,13800 r90 top (schematic designator D2)
D2_PD5 "1N914" 3216 8670,13800 r90 bottom (schematic designator D2)
D2_PD6 "1N914" 3216 7930,13800 r90 bottom (schematic designator D2)
D2_PD7 "1N914" 3216 7190,13800 r90 bottom (schematic designator D2)
D2_PD8 "1N914" 3216 6450,13800 r90 bottom (schematic designator D2)
D2_PD9 "1N914" 3216 7070,14460 r90 top (schematic designator D2)
D2_PD10 "1N914" 3216 7810,14460 r90 top (schematic designator D2)
D2_PD11 "1N914" 3216 8550,14460 r90 top (schematic designator D2)
D2_PD12 "1N914" 3216 9290,14460 r90 top (schematic designator D2)
D2_PD13 "1N914" 3216 8670,14460 r90 bottom (schematic designator D2)
D2_PD14 "1N914" 3216 7930,14460 r90 bottom (schematic designator D2)
D2_PD15 "1N914" 3216 7190,14460 r90 bottom (schematic designator D2)
D2_PD16 "1N914" 3216 6450,14460 r90 bottom (schematic designator D2)
D2_PD17 "1N914" 3216 7070,15120 r90 top (schematic designator D2)
D2_PD18 "1N914" 3216 7810,15120 r90 top (schematic designator D2)
D2_PD19 "1N914" 3216 8550,15120 r90 top (schematic designator D2)
D2_PD20 "1N914" 3216 9290,15120 r90 top (schematic designator D2)
D2_PD21 "1N914" 3216 8670,15120 r90 bottom (schematic designator D2)
D2_PD22 "1N914" 3216 7930,15120 r90 bottom (schematic designator D2)
D2_PD23 "1N914" 3216 7190,15120 r90 bottom (schematic designator D2)
D2_PD24 "1N914" 3216 6450,15120 r90 bottom (schematic designator D2)
D2_PD25 "1N914" 3216 7070,15780 r90 top (schematic designator D2)
D2_PD26 "1N914" 3216 7810,15780 r90 top (schematic designator D2)
D2_PD27 "1N914" 3216 8550,15780 r90 top (schematic designator D2)
D2_PD28 "1N914" 3216 9290,15780 r90 top (schematic designator D2)
D2_PD29 "1N914" 3216 8670,15780 r90 bottom (schematic designator D2)
D2_PD30 "1N914" 3216 7930,15780 r90 bottom (schematic designator D2)
D2_PD31 "1N914" 3216 7190,15780 r90 bottom (schematic designator D2)
D2_PD32 "1N914" 3216 6450,15780 r90 bottom (schematic designator D2)
JP1 "Header 10" HDR1X10 9445,14155 r90 top
JP2_BANK1 "Header 9X2A" FFC/SM0.5-2H18A 6270,13580 r270 bottom (schematic designator JP2)
JP2_BANK2 "Header 9X2A" FFC/SM0.5-2H18A 6270,14240 r270 bottom (schematic designator JP2)
JP2_BANK3 "Header 9X2A" FFC/SM0.5-2H18A 6270,14900 r270 bottom (schematic designator JP2)
JP2_BANK4 "Header 9X2A" FFC/SM0.5-2H18A 6270,15560 r270 bottom (schematic designator JP2)
Q1_PD1 "2N2222" SO-G3/D4.1 6490,13790 r270 top (schematic designator Q1)
Q1_PD2 "2N2222" SO-G3/D4.1 7230,13790 r270 top (schematic designator Q1)
Q1_PD3 "2N2222" SO-G3/D4.1 7970,13790 r270 top (schematic designator Q1)
Q1_PD4 "2N2222" SO-G3/D4.1 8710,13790 r270 top (schematic designator Q1)
Q1_PD5 "2N2222" SO-G3/D4.1 9250,13790 r270 bottom (schematic designator Q1)
Q1_PD6 "2N2222" SO-G3/D4.1 8510,13790 r270 bottom (schematic designator Q1)
Q1_PD7 "2N2222" SO-G3/D4.1 7770,13790 r270 bottom (schematic designator Q1)
Q1_PD8 "2N2222" SO-G3/D4.1 7030,13790 r270 bottom (schematic designator Q1)
Q1_PD9 "2N2222" SO-G3/D4.1 6490,14450 r270 top (schematic designator Q1)
Q1_PD10 "2N2222" SO-G3/D4.1 7230,14450 r270 top (schematic designator Q1)
Q1_PD11 "2N2222" SO-G3/D4.1 7970,14450 r270 top (schematic designator Q1)
Q1_PD12 "2N2222" SO-G3/D4.1 8710,14450 r270 top (schematic designator Q1)
Q1_PD13 "2N2222" SO-G3/D4.1 9250,14450 r270 bottom (schematic designator Q1)
Q1_PD14 "2N2222" SO-G3/D4.1 8510,14450 r270 bottom (schematic designator Q1)
Q1_PD15 "2N2222" SO-G3/D4.1 7770,14450 r270 bottom (schematic designator Q1)
Q1_PD16 "2N2222" SO-G3/D4.1 7030,14450 r270 bottom (schematic designator Q1)
Q1_PD17 "2N2222" SO-G3/D4.1 6490,15110 r270 top (schematic designator Q1)
Q1_PD18 "2N2222" SO-G3/D4.1 7230,15110 r270 top (schematic designator Q1)
Q1_PD19 "2N2222" SO-G3/D4.1 7970,15110 r270 top (schematic designator Q1)
Q1_PD20 "2N2222" SO-G3/D4.1 8710,15110 r270 top (schematic designator Q1)
Q1_PD21 "2N2222" SO-G3/D4.1 9250,15110 r270 bottom (schematic designator Q1)
Q1_PD22 "2N2222" SO-G3/D4.1 8510,15110 r270 bottom (schematic designator Q1)
Q1_PD23 "2N2222" SO-G3/D4.1 7770,15110 r270 bottom (schematic designator Q1)
Q1_PD24 "2N2222" SO-G3/D4.1 7030,15110 r270 bottom (schematic designator Q1)
Q1_PD25 "2N2222" SO-G3/D4.1 6490,15770 r270 top (schematic designator Q1)
Q1_PD26 "2N2222" SO-G3/D4.1 7230,15770 r270 top (schematic designator Q1)
Q1_PD27 "2N2222" SO-G3/D4.1 7970,15770 r270 top (schematic designator Q1)
Q1_PD28 "2N2222" SO-G3/D4.1 8710,15770 r270 top (schematic designator Q1)
Q1_PD29 "2N2222" SO-G3/D4.1 9250,15770 r270 bottom (schematic designator Q1)
Q1_PD30 "2N2222" SO-G3/D4.1 8510,15770 r270 bottom (schematic designator Q1)
Q1_PD31 "2N2222" SO-G3/D4.1 7770,15770 r270 bottom (schematic designator Q1)
Q1_PD32 "2N2222" SO-G3/D4.1 7030,15770 r270 bottom (schematic designator Q1)
R1_PD1 "1.5K" 0603 6896.86,13376.99 r270 top (schematic designator R1)
R1_PD2 "1.5K" 0603 7636.86,13376.99 r270 top (schematic designator R1)
R1_PD3 "1.5K" 0603 8376.86,13376.99 r270 top (schematic designator R1)
R1_PD4 "1.5K" 0603 9116.86,13376.99 r270 top (schematic designator R1)
R1_PD5 "1.5K" 0603 8843.14,13376.99 r270 bottom (schematic designator R1)
R1_PD6 "1.5K" 0603 8103.14,13376.99 r270 bottom (schematic designator R1)
R1_PD7 "1.5K" 0603 7363.14,13376.99 r270 bottom (schematic designator R1)
R1_PD8 "1.5K" 0603 6623.14,13376.99 r270 bottom (schematic designator R1)
R1_PD9 "1.5K" 0603 6896.86,14036.99 r270 top (schematic designator R1)
R1_PD10 "1.5K" 0603 7636.86,14036.99 r270 top (schematic designator R1)
R1_PD11 "1.5K" 0603 8376.86,14036.99 r270 top (schematic designator R1)
R1_PD12 "1.5K" 0603 9116.86,14036.99 r270 top (schematic designator R1)
R1_PD13 "1.5K" 0603 8843.14,14036.99 r270 bottom (schematic designator R1)
R1_PD14 "1.5K" 0603 8103.14,14036.99 r270 bottom (schematic designator R1)
R1_PD15 "1.5K" 0603 7363.14,14036.99 r270 bottom (schematic designator R1)
R1_PD16 "1.5K" 0603 6623.14,14036.99 r270 bottom (schematic designator R1)
R1_PD17 "1.5K" 0603 6896.86,14696.99 r270 top (schematic designator R1)
R1_PD18 "1.5K" 0603 7636.86,14696.99 r270 top (schematic designator R1)
R1_PD19 "1.5K" 0603 8376.86,14696.99 r270 top (schematic designator R1)
R1_PD20 "1.5K" 0603 9116.86,14696.99 r270 top (schematic designator R1)
R1_PD21 "1.5K" 0603 8843.14,14696.99 r270 bottom (schematic designator R1)
R1_PD22 "1.5K" 0603 8103.14,14696.99 r270 bottom (schematic designator R1)
R1_PD23 "1.5K" 0603 7363.14,14696.99 r270 bottom (schematic designator R1)
R1_PD24 "1.5K" 0603 6623.14,14696.99 r270 bottom (schematic designator R1)
R1_PD25 "1.5K" 0603 6896.86,15356.99 r270 top (schematic designator R1)
R1_PD26 "1.5K" 0603 7636.86,15356.99 r270 top (schematic designator R1)
R1_PD27 "1.5K" 0603 8376.86,15356.99 r270 top (schematic designator R1)
R1_PD28 "1.5K" 0603 9116.86,15356.99 r270 top (schematic designator R1)
R1_PD29 "1.5K" 0603 8843.14,15356.99 r270 bottom (schematic designator R1)
R1_PD30 "1.5K" 0603 8103.14,15356.99 r270 bottom (schematic designator R1)
R1_PD31 "1.5K" 0603 7363.14,15356.99 r270 bottom (schematic designator R1)
R1_PD32 "1.5K" 0603 6623.14,15356.99 r270 bottom (schematic designator R1)
R2_PD1 "2.2K" 0603 6713.71,13376.99 r270 top (schematic designator R2)
R2_PD2 "2.2K" 0603 7453.71,13376.99 r270 top (schematic designator R2)
R2_PD3 "2.2K" 0603 8193.71,13376.99 r270 top (schematic designator R2)
R2_PD4 "2.2K" 0603 8933.71,13376.99 r270 top (schematic designator R2)
R2_PD5 "2.2K" 0603 9026.29,13376.99 r270 bottom (schematic designator R2)
R2_PD6 "2.2K" 0603 8286.29,13376.99 r270 bottom (schematic designator R2)
R2_PD7 "2.2K" 0603 7546.29,13376.99 r270 bottom (schematic designator R2)
R2_PD8 "2.2K" 0603 6806.29,13376.99 r270 bottom (schematic designator R2)
R2_PD9 "2.2K" 0603 6713.71,14036.99 r270 top (schematic designator R2)
R2_PD10 "2.2K" 0603 7453.71,14036.99 r270 top (schematic designator R2)
R2_PD11 "2.2K" 0603 8193.71,14036.99 r270 top (schematic designator R2)
R2_PD12 "2.2K" 0603 8933.71,14036.99 r270 top (schematic designator R2)
R2_PD13 "2.2K" 0603 9026.29,14036.99 r270 bottom (schematic designator R2)
R2_PD14 "2.2K" 0603 8286.29,14036.99 r270 bottom (schematic designator R2)
R2_PD15 "2.2K" 0603 7546.29,14036.99 r270 bottom (schematic designator R2)
R2_PD16 "2.2K" 0603 6806.29,14036.99 r270 bottom (schematic designator R2)
R2_PD17 "2.2K" 0603 6713.71,14696.99 r270 top (schematic designator R2)
R2_PD18 "2.2K" 0603 7453.71,14696.99 r270 top (schematic designator R2)
R2_PD19 "2.2K" 0603 8193.71,14696.99 r270 top (schematic designator R2)
R2_PD20 "2.2K" 0603 8933.71,14696.99 r270 top (schematic designator R2)
R2_PD21 "2.2K" 0603 9026.29,14696.99 r270 bottom (schematic designator R2)
R2_PD22 "2.2K" 0603 8286.29,14696.99 r270 bottom (schematic designator R2)
R2_PD23 "2.2K" 0603 7546.29,14696.99 r270 bottom (schematic designator R2)
R2_PD24 "2.2K" 0603 6806.29,14696.99 r270 bottom (schematic designator R2)
R2_PD25 "2.2K" 0603 6713.71,15356.99 r270 top (schematic designator R2)
R2_PD26 "2.2K" 0603 7453.71,15356.99 r270 top (schematic designator R2)
R2_PD27 "2.2K" 0603 8193.71,15356.99 r270 top (schematic designator R2)
R2_PD28 "2.2K" 0603 8933.71,15356.99 r270 top (schematic designator R2)
R2_PD29 "2.2K" 0603 9026.29,15356.99 r270 bottom (schematic designator R2)
R2_PD30 "2.2K" 0603 8286.29,15356.99 r270 bottom (schematic designator R2)
R2_PD31 "2.2K" 0603 7546.29,15356.99 r270 bottom (schematic designator R2)
R2_PD32 "2.2K" 0603 6806.29,15356.99 r270 bottom (schematic designator R2)
R3_PD1 "100K" 0603 6622.14,13322 r90 top (schematic designator R3)
R3_PD2 "100K" 0603 7362.14,13322 r90 top (schematic designator R3)
R3_PD3 "100K" 0603 8102.14,13322 r90 top (schematic designator R3)
R3_PD4 "100K" 0603 8842.14,13322 r90 top (schematic designator R3)
R3_PD5 "100K" 0603 9117.86,13322 r90 bottom (schematic designator R3)
R3_PD6 "100K" 0603 8377.86,13322 r90 bottom (schematic designator R3)
R3_PD7 "100K" 0603 7637.86,13322 r90 bottom (schematic designator R3)
R3_PD8 "100K" 0603 6897.86,13322 r90 bottom (schematic designator R3)
R3_PD9 "100K" 0603 6622.14,13982 r90 top (schematic designator R3)
R3_PD10 "100K" 0603 7362.14,13982 r90 top (schematic designator R3)
R3_PD11 "100K" 0603 8102.14,13982 r90 top (schematic designator R3)
R3_PD12 "100K" 0603 8842.14,13982 r90 top (schematic designator R3)
R3_PD13 "100K" 0603 9117.86,13982 r90 bottom (schematic designator R3)
R3_PD14 "100K" 0603 8377.86,13982 r90 bottom (schematic designator R3)
R3_PD15 "100K" 0603 7637.86,13982 r90 bottom (schematic designator R3)
R3_PD16 "100K" 0603 6897.86,13982 r90 bottom (schematic designator R3)
R3_PD17 "100K" 0603 6622.14,14642 r90 top (schematic designator R3)
R3_PD18 "100K" 0603 7362.14,14642 r90 top (schematic designator R3)
R3_PD19 "100K" 0603 8102.14,14642 r90 top (schematic designator R3)
R3_PD20 "100K" 0603 8842.14,14642 r90 top (schematic designator R3)
R3_PD21 "100K" 0603 9117.86,14642 r90 bottom (schematic designator R3)
R3_PD22 "100K" 0603 8377.86,14642 r90 bottom (schematic designator R3)
R3_PD23 "100K" 0603 7637.86,14642 r90 bottom (schematic designator R3)
R3_PD24 "100K" 0603 6897.86,14642 r90 bottom (schematic designator R3)
R3_PD25 "100K" 0603 6622.14,15302 r90 top (schematic designator R3)
R3_PD26 "100K" 0603 7362.14,15302 r90 top (schematic designator R3)
R3_PD27 "100K" 0603 8102.14,15302 r90 top (schematic designator R3)
R3_PD28 "100K" 0603 8842.14,15302 r90 top (schematic designator R3)
R3_PD29 "100K" 0603 9117.86,15302 r90 bottom (schematic designator R3)
R3_PD30 "100K" 0603 8377.86,15302 r90 bottom (schematic designator R3)
R3_PD31 "100K" 0603 7637.86,15302 r90 bottom (schematic designator R3)
R3_PD32 "100K" 0603 6897.86,15302 r90 bottom (schematic designator R3)
R4_PD1 "10K" 0603 6530.57,13376.99 r270 top (schematic designator R4)
R4_PD2 "10K" 0603 7270.57,13376.99 r270 top (schematic designator R4)
R4_PD3 "10K" 0603 8010.57,13376.99 r270 top (schematic designator R4)
R4_PD4 "10K" 0603 8750.57,13376.99 r270 top (schematic designator R4)
R4_PD5 "10K" 0603 9209.43,13376.99 r270 bottom (schematic designator R4)
R4_PD6 "10K" 0603 8469.43,13376.99 r270 bottom (schematic designator R4)
R4_PD7 "10K" 0603 7729.43,13376.99 r270 bottom (schematic designator R4)
R4_PD8 "10K" 0603 6989.43,13376.99 r270 bottom (schematic designator R4)
R4_PD9 "10K" 0603 6530.57,14036.99 r270 top (schematic designator R4)
R4_PD10 "10K" 0603 7270.57,14036.99 r270 top (schematic designator R4)
R4_PD11 "10K" 0603 8010.57,14036.99 r270 top (schematic designator R4)
R4_PD12 "10K" 0603 8750.57,14036.99 r270 top (schematic designator R4)
R4_PD13 "10K" 0603 9209.43,14036.99 r270 bottom (schematic designator R4)
R4_PD14 "10K" 0603 8469.43,14036.99 r270 bottom (schematic designator R4)
R4_PD15 "10K" 0603 7729.43,14036.99 r270 bottom (schematic designator R4)
R4_PD16 "10K" 0603 6989.43,14036.99 r270 bottom (schematic designator R4)
R4_PD17 "10K" 0603 6530.57,14696.99 r270 top (schematic designator R4)
R4_PD18 "10K" 0603 7270.57,14696.99 r270 top (schematic designator R4)
R4_PD19 "10K" 0603 8010.57,14696.99 r270 top (schematic designator R4)
R4_PD20 "10K" 0603 8750.57,14696.99 r270 top (schematic designator R4)
R4_PD21 "10K" 0603 9209.43,14696.99 r270 bottom (schematic designator R4)
R4_PD22 "10K" 0603 8469.43,14696.99 r270 bottom (schematic designator R4)
R4_PD23 "10K" 0603 7729.43,14696.99 r270 bottom (schematic designator R4)
R4_PD24 "10K" 0603 6989.43,14696.99 r270 bottom (schematic designator R4)
R4_PD25 "10K" 0603 6530.57,15356.99 r270 top (schematic designator R4)
R4_PD26 "10K" 0603 7270.57,15356.99 r270 top (schematic designator R4)
R4_PD27 "10K" 0603 8010.57,15356.99 r270 top (schematic designator R4)
R4_PD28 "10K" 0603 8750.57,15356.99 r270 top (schematic designator R4)
R4_PD29 "10K" 0603 9209.43,15356.99 r270 bottom (schematic designator R4)
R4_PD30 "10K" 0603 8469.43,15356.99 r270 bottom (schematic designator R4)
R4_PD31 "10K" 0603 7729.43,15356.99 r270 bottom (schematic designator R4)
R4_PD32 "10K" 0603 6989.43,15356.99 r270 bottom (schematic designator R4)
R5_PD1 "1K" 0603 6439,13322 r90 top (schematic designator R5)
R5_PD2 "1K" 0603 7179,13322 r90 top (schematic designator R5)
R5_PD3 "1K" 0603 7919,13322 r90 top (schematic designator R5)
R5_PD4 "1K" 0603 8659,13322 r90 top (schematic designator R5)
R5_PD5 "1K" 0603 9301,13322 r90 bottom (schematic designator R5)
R5_PD6 "1K" 0603 8561,13322 r90 bottom (schematic designator R5)
R5_PD7 "1K" 0603 7821,13322 r90 bottom (schematic designator R5)
R5_PD8 "1K" 0603 7081,13322 r90 bottom (schematic designator R5)
R5_PD9 "1K" 0603 6439,13982 r90 top (schematic designator R5)
R5_PD10 "1K" 0603 7179,13982 r90 top (schematic designator R5)
R5_PD11 "1K" 0603 7919,13982 r90 top (schematic designator R5)
R5_PD12 "1K" 0603 8659,13982 r90 top (schematic designator R5)
R5_PD13 "1K" 0603 9301,13982 r90 bottom (schematic designator R5)
R5_PD14 "1K" 0603 8561,13982 r90 bottom (schematic designator R5)
R5_PD15 "1K" 0603 7821,13982 r90 bottom (schematic designator R5)
R5_PD16 "1K" 0603 7081,13982 r90 bottom (schematic designator R5)
R5_PD17 "1K" 0603 6439,14642 r90 top (schematic designator R5)
R5_PD18 "1K" 0603 7179,14642 r90 top (schematic designator R5)
R5_PD19 "1K" 0603 7919,14642 r90 top (schematic designator R5)
R5_PD20 "1K" 0603 8659,14642 r90 top (schematic designator R5)
R5_PD21 "1K" 0603 9301,14642 r90 bottom (schematic designator R5)
R5_PD22 "1K" 0603 8561,14642 r90 bottom (schematic designator R5)
R5_PD23 "1K" 0603 7821,14642 r90 bottom (schematic designator R5)
R5_PD24 "1K" 0603 7081,14642 r90 bottom (schematic designator R5)
R5_PD25 "1K" 0603 6439,15302 r90 top (schematic designator R5)
R5_PD26 "1K" 0603 7179,15302 r90 top (schematic designator R5)
R5_PD27 "1K" 0603 7919,15302 r90 top (schematic designator R5)
R5_PD28 "1K" 0603 8659,15302 r90 top (schematic designator R5)
R5_PD29 "1K" 0603 9301,15302 r90 bottom (schematic designator R5)
R5_PD30 "1K" 0603 8561,15302 r90 bottom (schematic designator R5)
R5_PD31 "1K" 0603 7821,15302 r90 bottom (schematic designator R5)
R5_PD32 "1K" 0603 7081,15302 r90 bottom (schematic designator R5)
R6_PD1 "10K" 0603 6988.43,13322 r90 top (schematic designator R6)
R6_PD2 "10K" 0603 7728.43,13322 r90 top (schematic designator R6)
R6_PD3 "10K" 0603 8468.43,13322 r90 top (schematic designator R6)
R6_PD4 "10K" 0603 9208.43,13322 r90 top (schematic designator R6)
R6_PD5 "10K" 0603 8751.57,13322 r90 bottom (schematic designator R6)
R6_PD6 "10K" 0603 8011.57,13322 r90 bottom (schematic designator R6)
R6_PD7 "10K" 0603 7271.57,13322 r90 bottom (schematic designator R6)
R6_PD8 "10K" 0603 6531.57,13322 r90 bottom (schematic designator R6)
R6_PD9 "10K" 0603 6988.43,13982 r90 top (schematic designator R6)
R6_PD10 "10K" 0603 7728.43,13982 r90 top (schematic designator R6)
R6_PD11 "10K" 0603 8468.43,13982 r90 top (schematic designator R6)
R6_PD12 "10K" 0603 9208.43,13982 r90 top (schematic designator R6)
R6_PD13 "10K" 0603 8751.57,13982 r90 bottom (schematic designator R6)
R6_PD14 "10K" 0603 8011.57,13982 r90 bottom (schematic designator R6)
R6_PD15 "10K" 0603 7271.57,13982 r90 bottom (schematic designator R6)
R6_PD16 "10K" 0603 6531.57,13982 r90 bottom (schematic designator R6)
R6_PD17 "10K" 0603 6988.43,14642 r90 top (schematic designator R6)
R6_PD18 "10K" 0603 7728.43,14642 r90 top (schematic designator R6)
R6_PD19 "10K" 0603 8468.43,14642 r90 top (schematic designator R6)
R6_PD20 "10K" 0603 9208.43,14642 r90 top (schematic designator R6)
R6_PD21 "10K" 0603 8751.57,14642 r90 bottom (schematic designator R6)
R6_PD22 "10K" 0603 8011.57,14642 r90 bottom (schematic designator R6)
R6_PD23 "10K" 0603 7271.57,14642 r90 bottom (schematic designator R6)
R6_PD24 "10K" 0603 6531.57,14642 r90 bottom (schematic designator R6)
R6_PD25 "10K" 0603 6988.43,15302 r90 top (schematic designator R6)
R6_PD26 "10K" 0603 7728.43,15302 r90 top (schematic designator R6)
R6_PD27 "10K" 0603 8468.43,15302 r90 top (schematic designator R6)
R6_PD28 "10K" 0603 9208.43,15302 r90 top (schematic designator R6)
R6_PD29 "10K" 0603 8751.57,15302 r90 bottom (schematic designator R6)
R6_PD30 "10K" 0603 8011.57,15302 r90 bottom (schematic designator R6)
R6_PD31 "10K" 0603 7271.57,15302 r90 bottom (schematic designator R6)
R6_PD32 "10K" 0603 6531.57,15302 r90 bottom (schematic designator R6)
R8_PD1 "22K" 0603 7080,13320 r90 top (schematic designator R8)
R8_PD2 "22K" 0603 7820,13320 r90 top (schematic designator R8)
R8_PD3 "22K" 0603 8560,13320 r90 top (schematic designator R8)
R8_PD4 "22K" 0603 9300,13320 r90 top (schematic designator R8)
R8_PD5 "22K" 0603 8660,13320 r90 bottom (schematic designator R8)
R8_PD6 "22K" 0603 7920,13320 r90 bottom (schematic designator R8)
R8_PD7 "22K" 0603 7180,13320 r90 bottom (schematic designator R8)
R8_PD8 "22K" 0603 6440,13320 r90 bottom (schematic designator R8)
R8_PD9 "22K" 0603 7080,13980 r90 top (schematic designator R8)
R8_PD10 "22K" 0603 7820,13980 r90 top (schematic designator R8)
R8_PD11 "22K" 0603 8560,13980 r90 top (schematic designator R8)
R8_PD12 "22K" 0603 9300,13980 r90 top (schematic designator R8)
R8_PD13 "22K" 0603 8660,13980 r90 bottom (schematic designator R8)
R8_PD14 "22K" 0603 7920,13980 r90 bottom (schematic designator R8)
R8_PD15 "22K" 0603 7180,13980 r90 bottom (schematic designator R8)
R8_PD16 "22K" 0603 6440,13980 r90 bottom (schematic designator R8)
R8_PD17 "22K" 0603 7080,14640 r90 top (schematic designator R8)
R8_PD18 "22K" 0603 7820,14640 r90 top (schematic designator R8)
R8_PD19 "22K" 0603 8560,14640 r90 top (schematic designator R8)
R8_PD20 "22K" 0603 9300,14640 r90 top (schematic designator R8)
R8_PD21 "22K" 0603 8660,14640 r90 bottom (schematic designator R8)
R8_PD22 "22K" 0603 7920,14640 r90 bottom (schematic designator R8)
R8_PD23 "22K" 0603 7180,14640 r90 bottom (schematic designator R8)
R8_PD24 "22K" 0603 6440,14640 r90 bottom (schematic designator R8)
R8_PD25 "22K" 0603 7080,15300 r90 top (schematic designator R8)
R8_PD26 "22K" 0603 7820,15300 r90 top (schematic designator R8)
R8_PD27 "22K" 0603 8560,15300 r90 top (schematic designator R8)
R8_PD28 "22K" 0603 9300,15300 r90 top (schematic designator R8)
R8_PD29 "22K" 0603 8660,15300 r90 bottom (schematic designator R8)
R8_PD30 "22K" 0603 7920,15300 r90 bottom (schematic designator R8)
R8_PD31 "22K" 0603 7180,15300 r90 bottom (schematic designator R8)
R8_PD32 "22K" 0603 6440,15300 r90 bottom (schematic designator R8)
R88_PD1 "1.0" 0603 6970,13680 r90 top (schematic designator R88)
R88_PD2 "1.0" 0603 7710,13680 r90 top (schematic designator R88)
R88_PD3 "1.0" 0603 8450,13680 r90 top (schematic designator R88)
R88_PD4 "1.0" 0603 9190,13680 r90 top (schematic designator R88)
R88_PD5 "1.0" 0603 8770,13680 r90 bottom (schematic designator R88)
R88_PD6 "1.0" 0603 8030,13680 r90 bottom (schematic designator R88)
R88_PD7 "1.0" 0603 7290,13680 r90 bottom (schematic designator R88)
R88_PD8 "1.0" 0603 6550,13680 r90 bottom (schematic designator R88)
R88_PD9 "1.0" 0603 6970,14340 r90 top (schematic designator R88)
R88_PD10 "1.0" 0603 7710,14340 r90 top (schematic designator R88)
R88_PD11 "1.0" 0603 8450,14340 r90 top (schematic designator R88)
R88_PD12 "1.0" 0603 9190,14340 r90 top (schematic designator R88)
R88_PD13 "1.0" 0603 8770,14340 r90 bottom (schematic designator R88)
R88_PD14 "1.0" 0603 8030,14340 r90 bottom (schematic designator R88)
R88_PD15 "1.0" 0603 7290,14340 r90 bottom (schematic designator R88)
R88_PD16 "1.0" 0603 6550,14340 r90 bottom (schematic designator R88)
R88_PD17 "1.0" 0603 6970,15000 r90 top (schematic designator R88)
R88_PD18 "1.0" 0603 7710,15000 r90 top (schematic designator R88)
R88_PD19 "1.0" 0603 8450,15000 r90 top (schematic designator R88)
R88_PD20 "1.0" 0603 9190,15000 r90 top (schematic designator R88)
R88_PD21 "1.0" 0603 8770,15000 r90 bottom (schematic designator R88)
R88_PD22 "1.0" 0603 8030,15000 r90 bottom (schematic designator R88)
R88_PD23 "1.0" 0603 7290,15000 r90 bottom (schematic designator R88)
R88_PD24 "1.0" 0603 6550,15000 r90 bottom (schematic designator R88)
R88_PD25 "1.0" 0603 6970,15660 r90 top (schematic designator R88)
R88_PD26 "1.0" 0603 7710,15660 r90 top (schematic designator R88)
R88_PD27 "1.0" 0603 8450,15660 r90 top (schematic designator R88)
R88_PD28 "1.0" 0603 9190,15660 r90 top (schematic designator R88)
R88_PD29 "1.0" 0603 8770,15660 r90 bottom (schematic designator R88)
R88_PD30 "1.0" 0603 8030,15660 r90 bottom (schematic designator R88)
R88_PD31 "1.0" 0603 7290,15660 r90 bottom (schematic designator R88)
R88_PD32 "1.0" 0603 6550,15660 r90 bottom (schematic designator R88)
RPOT_PD1 "2.5K" 0603 6805.29,13376.99 r270 top (schematic designator RPOT)
RPOT_PD2 "2.5K" 0603 7545.29,13376.99 r270 top (schematic designator RPOT)
RPOT_PD3 "2.5K" 0603 8285.29,13376.99 r270 top (schematic designator RPOT)
RPOT_PD4 "2.5K" 0603 9025.29,13376.99 r270 top (schematic designator RPOT)
RPOT_PD5 "2.5K" 0603 8934.71,13376.99 r270 bottom (schematic designator RPOT)
RPOT_PD6 "2.5K" 0603 8194.71,13376.99 r270 bottom (schematic designator RPOT)
RPOT_PD7 "2.5K" 0603 7454.71,13376.99 r270 bottom (schematic designator RPOT)
RPOT_PD8 "2.5K" 0603 6714.71,13376.99 r270 bottom (schematic designator RPOT)
RPOT_PD9 "2.5K" 0603 6805.29,14036.99 r270 top (schematic designator RPOT)
RPOT_PD10 "2.5K" 0603 7545.29,14036.99 r270 top (schematic designator RPOT)
RPOT_PD11 "2.5K" 0603 8285.29,14036.99 r270 top (schematic designator RPOT)
RPOT_PD12 "2.5K" 0603 9025.29,14036.99 r270 top (schematic designator RPOT)
RPOT_PD13 "2.5K" 0603 8934.71,14036.99 r270 bottom (schematic designator RPOT)
RPOT_PD14 "2.5K" 0603 8194.71,14036.99 r270 bottom (schematic designator RPOT)
RPOT_PD15 "2.5K" 0603 7454.71,14036.99 r270 bottom (schematic designator RPOT)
